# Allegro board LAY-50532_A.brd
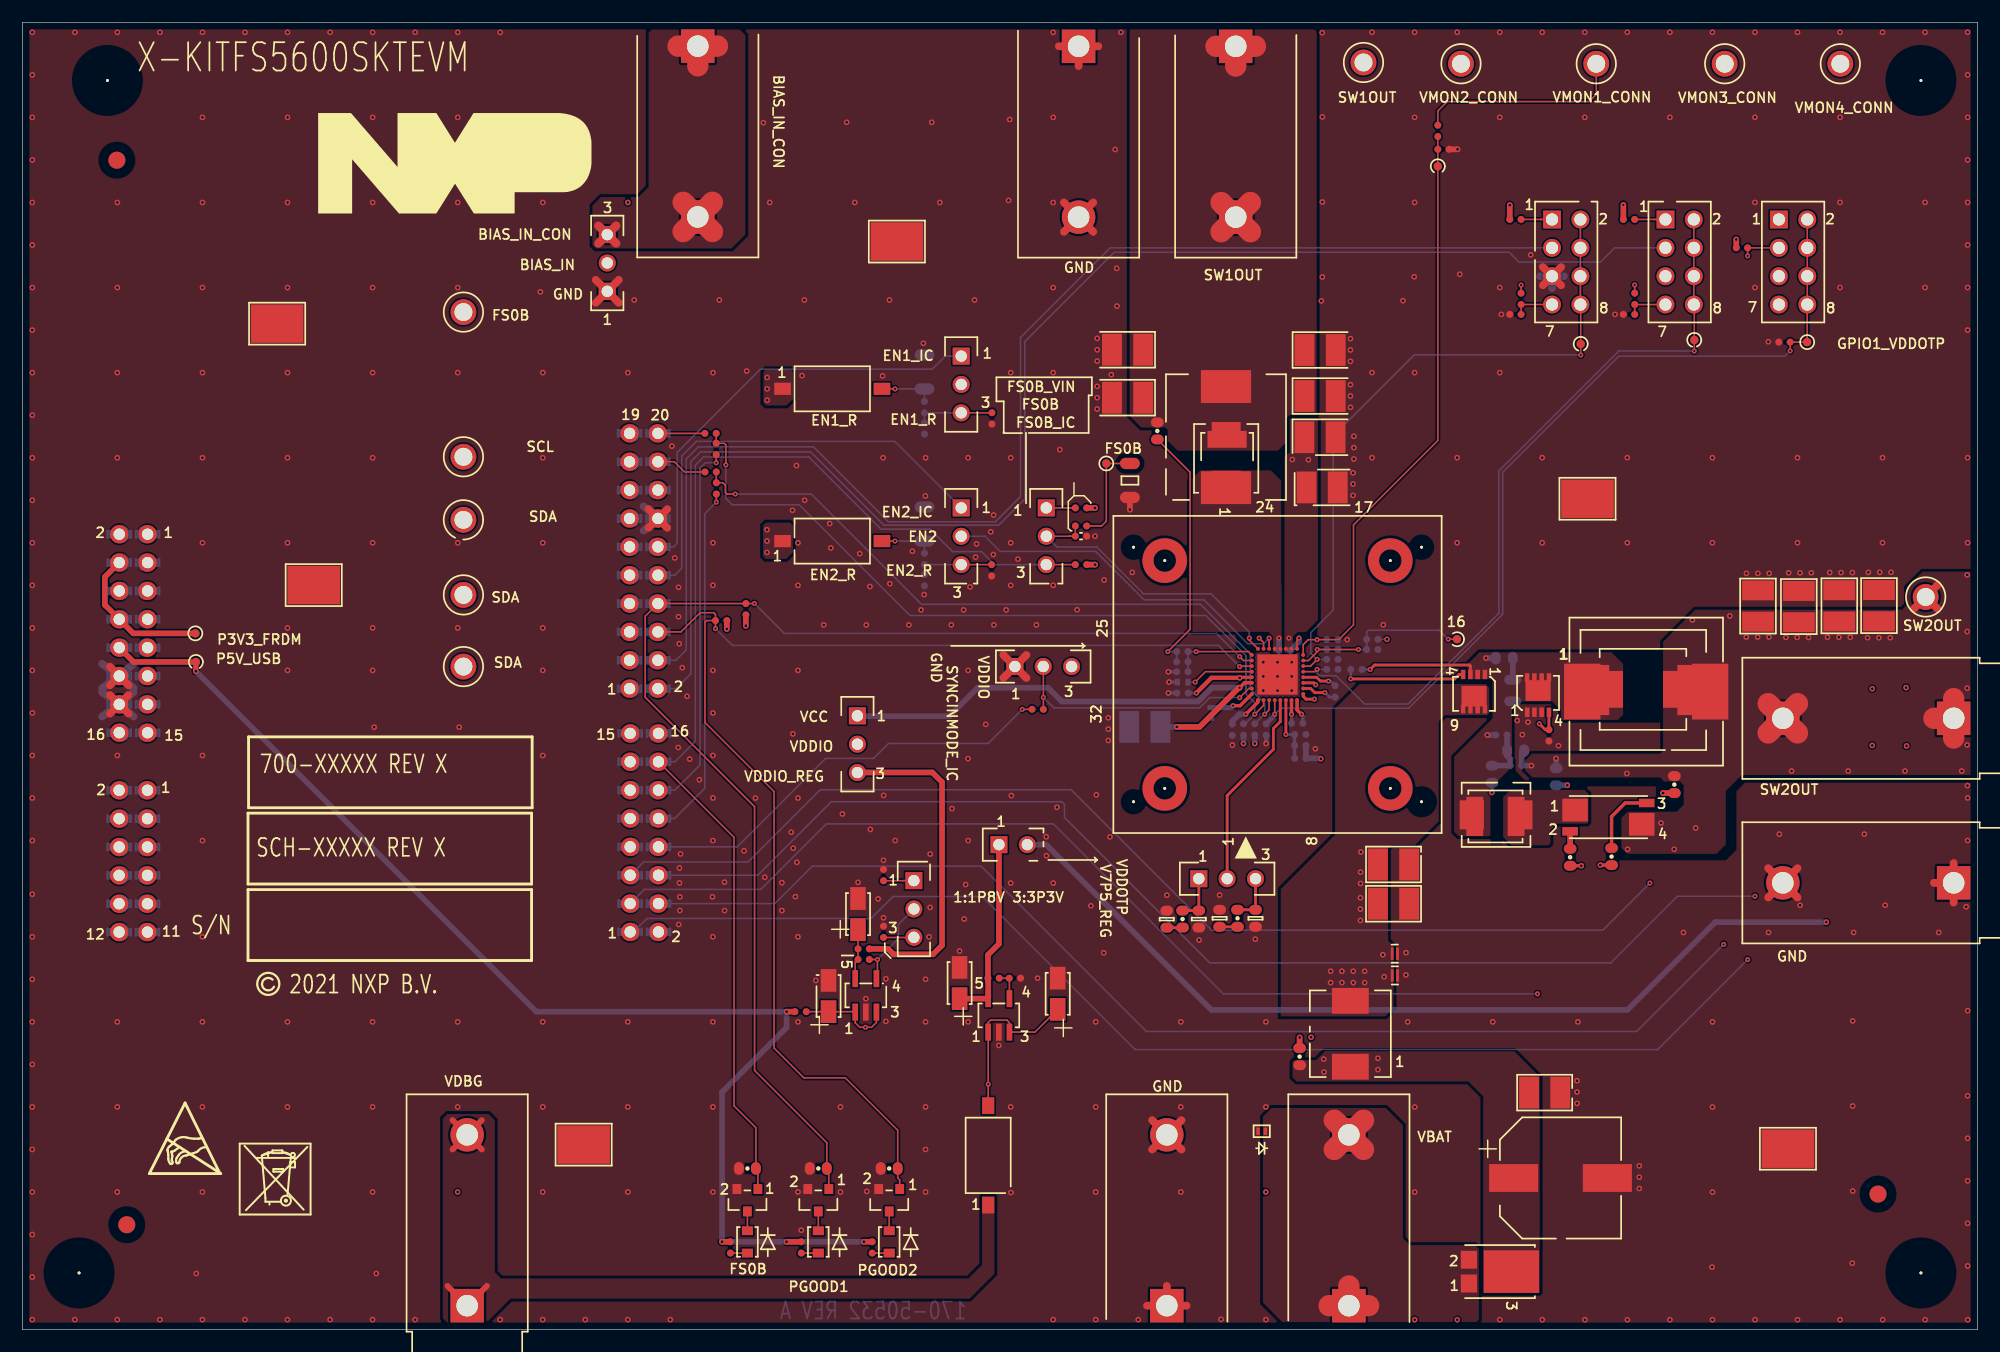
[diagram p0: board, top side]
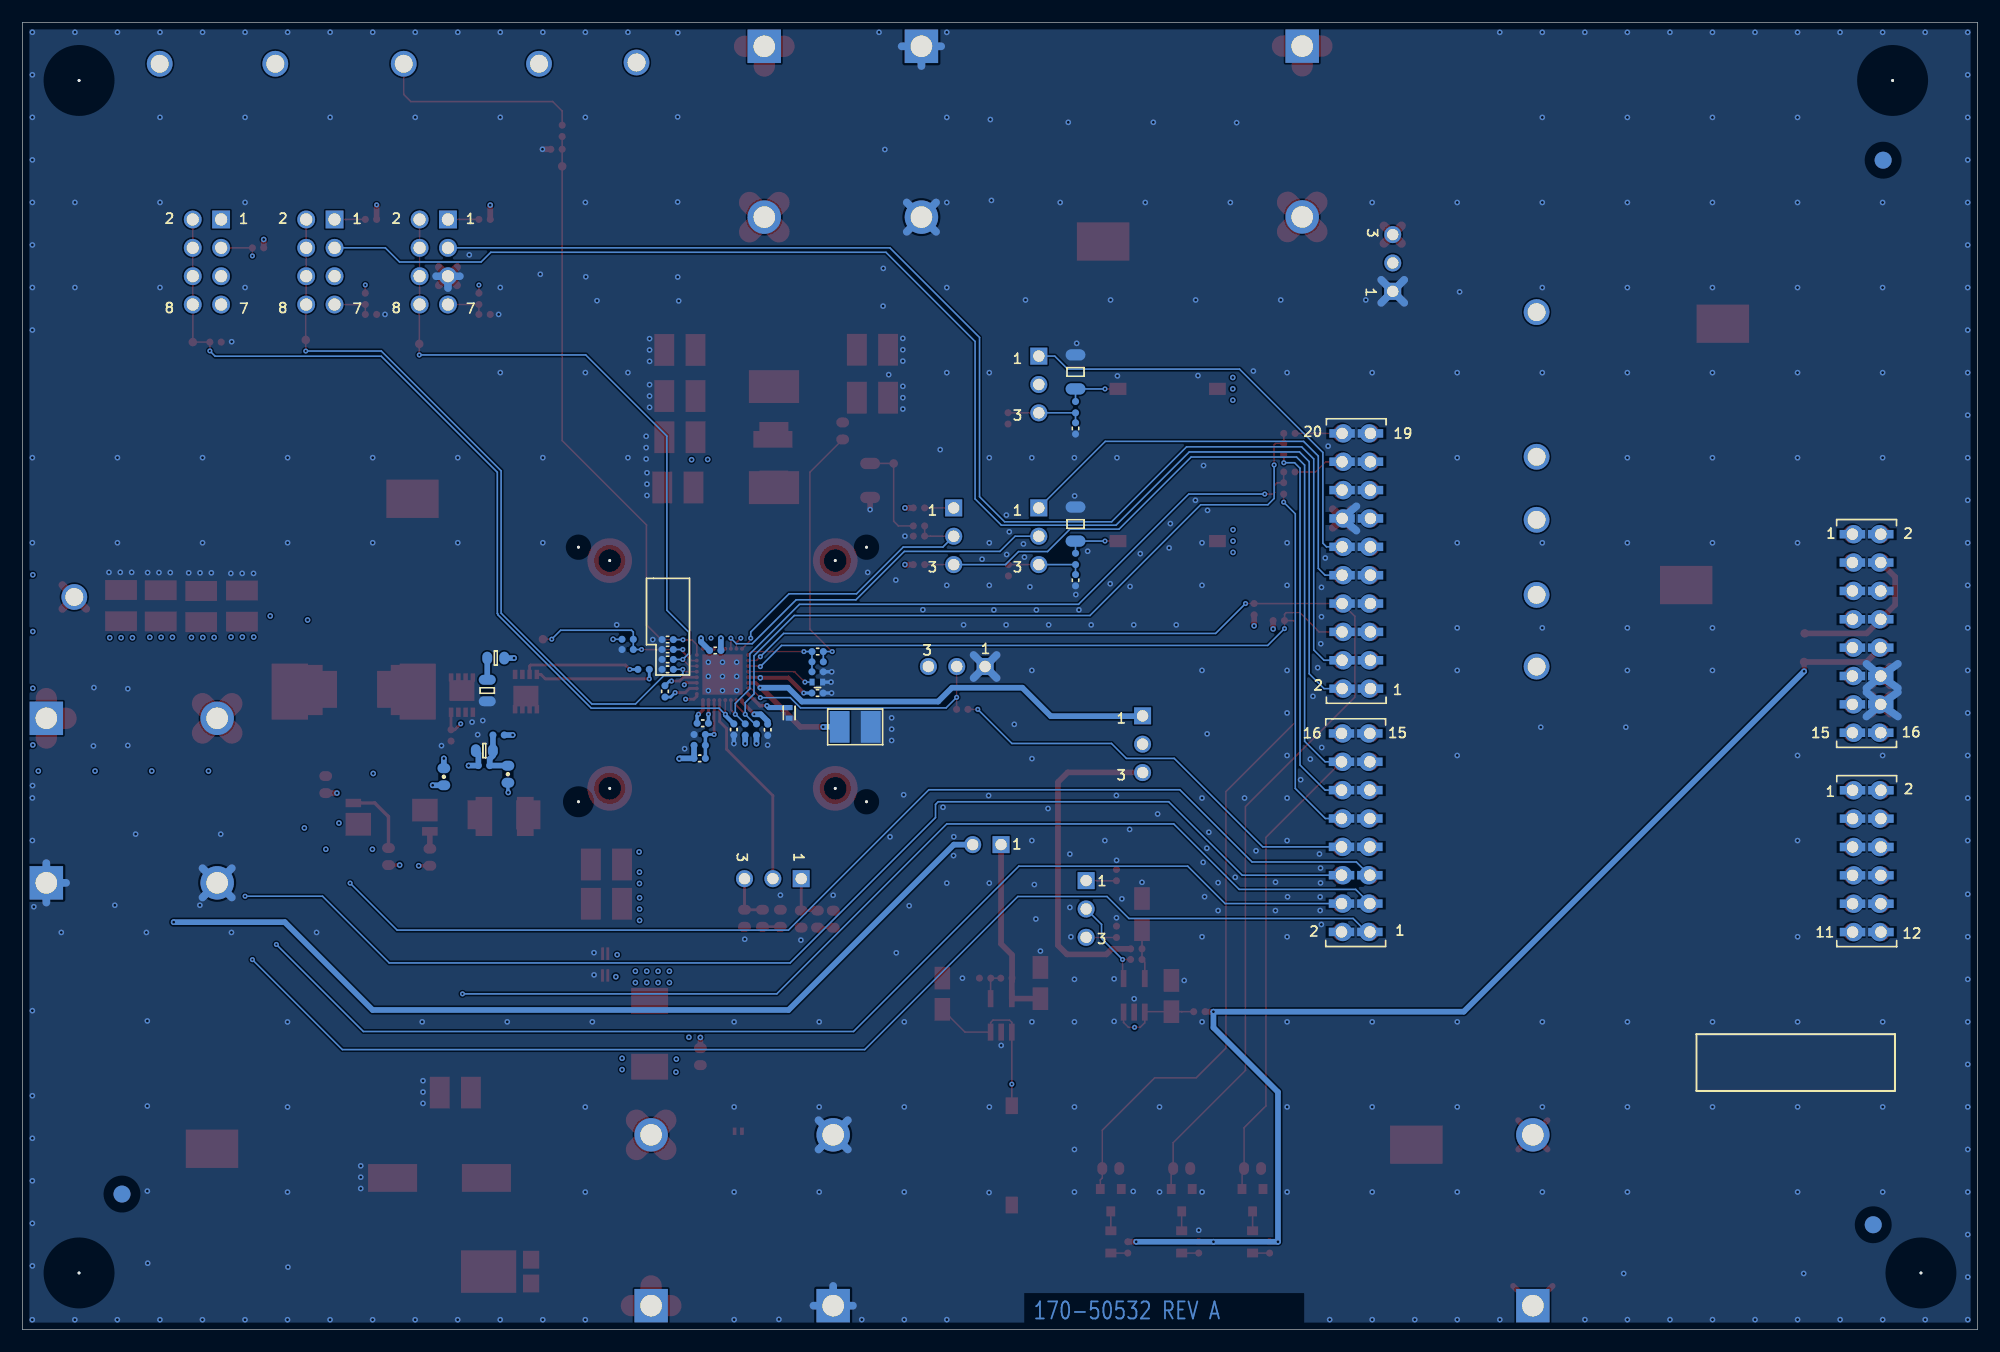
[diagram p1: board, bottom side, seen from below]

Outline 175.13 x 117.09 mm; copper layers: TOP, L2_GND1, L3_INT1, L4_PWR1, L5_GND2, L6_PWR2, L7_GND3, BOTTOM. Coordinates in mm from the lower left corner of the outline.
Outline path: 0,117.09 175.13,117.09 175.13,0 0,0 0,117.09

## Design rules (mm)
constraint set DEFAULT: min track width 0.14
net group POWER: nets VCC VDDIO

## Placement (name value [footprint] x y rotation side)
C1  10uF  [CC1210]  136.35 21.23 0 top
C2  47uF  [CAP_ALEL_10P5SQ_SMT]  137.77 13.59 90 top
C3  0.022UF  [CC1206_OV]  80.8 85.78 90 bottom
C4  6800pF  [CC0402_25]  80.8 80.72 270 bottom
C5  0.022UF  [CC1206_OV]  80.8 72.16 90 bottom
C6  6800pF  [CC0402_25]  80.8 67.13 270 bottom
C7  1uF  [CC0402_TOL0P2]  106.45 55.24 270 bottom
C8  0.1uF  [CC0402_25]  103.91 57.02 180 bottom
C9  10uF  [CC1210]  100.54 53.99 180 bottom
C10  2.2uF  [CC0402_TOL0P2]  103.93 58 180 bottom
C11  0.1uF  [CC0402_25]  108.37 53.73 270 bottom
C12  0.1uF  [CC0402_25]  113.07 60.83 180 bottom
C13  CGA6P1X7R1C226M250AC  [CC1210]  116.24 83.62 0 top
C14  CGA6P1X7R1C226M250AC  [CC1210]  116.24 87.75 0 top
C15  CGA6P1X7R1C226M250AC  [CC1210]  98.99 87.77 180 top
C16  CGA6P1X7R1C226M250AC  [CC1210]  98.99 83.48 180 top
C17  10uF  [CC1210]  116.23 79.93 0 top
C18  10uF  [CC1210]  116.42 75.44 0 top
C19  0.1uF  [CC0402_25]  117.58 57.17 270 bottom
C20  10uF  [CC1210]  122.82 41.67 0 top
C22  10uF  [CC1210]  122.82 38.15 0 top
C24  CGA6P1X7R1C226M250AC  [CC1210]  155.46 64.81 90 top
C25  CGA6P1X7R1C226M250AC  [CC1210]  159.12 64.77 90 top
C26  CGA6P1X7R1C226M250AC  [CC1210]  162.74 64.83 90 top
C27  CGA6P1X7R1C226M250AC  [CC1210]  166.29 64.85 90 top
C32  0.01UF  [CC0402_25]  117.33 61.81 0 bottom
C33  0.01UF  [CC0402_25]  117.33 60.92 0 bottom
C34  0.01UF  [CC0402_25]  117.33 60.03 0 bottom
C37  6800pF  [CC0402_25]  114.19 54.31 180 bottom
C42  0.022UF  [CC1206_OV]  99.2 76.06 270 top
C43  6800pF  [CC0402_25]  94.82 71.07 0 top
C44  1uF  [CC0402_25]  111.4 53.75 270 bottom
C45  2.2UF  [CC3216]  72.21 29.88 90 top
C46  2.2UF  [CC3216]  74.85 37.22 90 top
C47  2.2UF  [CC3216]  92.74 30.09 90 top
C48  2.2UF  [CC3216]  83.95 31.05 90 top
C49  2200pF  [CC0402_25]  103.9 60.73 0 bottom
C50  2200pF  [CC0402_25]  114.46 51.17 180 bottom
C51  2200PF  [CC0603_OV]  132.73 60.15 0 bottom
C52  0.1uF  [CC0603_OV]  133.75 51.86 0 bottom
C53  0.01UF  [CC0402_25]  117.33 59.14 0 bottom
C54  0.047uF  [CC0204]  122.93 31.73 0 top
C55  0.047uF  [CC0204]  122.93 33.68 0 top
CCOMP1  0.022UF  [CC0603_OV]  102.5 36.77 90 top
CCOMP2  0.022UF  [CC0603_OV]  107.23 36.85 90 top
CHF1  20pF  [CC0603_OV]  105.37 36.77 270 top
CHF2  20pF  [CC0603_OV]  110.45 36.85 270 top
D1  PMEG060V050EPD  [SOT1289]  132.34 5.2 270 top
D2  AQHV36-01ETG  [DIODE_SOD882_SM_0P7X1P1]  111.01 17.77 0 top
D7  RED  [LED2_2P1X1P5_NSP]  71.29 7.86 270 top
D8  RED  [LED2_2P1X1P5_NSP]  77.64 7.86 270 top
D9  RED  [LED2_2P1X1P5_NSP]  64.94 7.86 270 top
GPIO2_VMON3  -  [TPAD_030]  139.58 88.29 0 top
GPIO3_VMON4  -  [TPAD_030]  149.75 88.65 0 top
J3  HDR 1X3  [HDR103]  84.09 87.2 0 top
J4  HDR 1X3  [HDR103]  84.09 73.6 0 top
J5  HDR 1X3  [HDR103]  88.9 59.4 90 top
J6  5-146257-8  [HDR208_197X789_TH]  54.44 35.62 0 bottom
J8  HDR 1X3  [HDR103]  91.71 73.6 0 top
J12  HDR 2X4  [HDR2X4_2P54_TH]  137.01 99.44 0 top
J13  HDR 2X4  [HDR2X4_2P54_TH]  147.17 99.44 0 top
J14  HDR 2X4  [HDR2X4_2P54_TH]  157.33 99.44 0 top
J21  SKT RED  [CON_BANANA_571]  118.81 2.15 180 top
J22  SKT RED  [CON_BANANA_571]  60.5 114.96 0 top
J23  SKT RED  [CON_BANANA_571]  108.68 114.95 0 top
J24  SKT RED  [CON_BANANA_571]  172.98 54.76 270 top
J25  SKT BLACK  [CON_BANANA_571]  102.51 2.15 180 top
J27  SKT BLACK  [CON_BANANA_571]  94.6 114.95 0 top
J28  SKT BLACK  [CON_BANANA_571]  172.98 40.02 270 top
J29  HDR 1X3  [HDR103]  52.39 93 180 top
J30  HDR_1X3  [HDR103]  79.85 40.22 0 top
J32  HDR 1X2  [HDR102]  87.47 43.44 90 top
J73  6-146257-0  [HDR210_197X989_TH]  54.39 57.42 0 bottom
J75  5-146257-6  [HDR206_197X589_TH]  11.21 48.31 180 bottom
J91  5-146257-8  [HDR208_197X789_TH]  11.22 71.25 180 bottom
J92  SKT RED  [CON_BANANA_571]  39.84 2.15 180 top
J93  HDR 1X3  [HDR103]  74.8 54.98 0 top
J94  HDR 1X3  [HDR103]  105.37 40.39 90 top
L1  1uH  [IND2_7P4X6P9_SM]  118.95 26.51 90 top
L2  4.7uH  [IND2_10P9X10P4]  145.19 57.29 0 top
L3  VCHA042A-1R5MS6  [IND2_4P5X4P3]  107.91 77.9 90 top
L5  VCHA042A-1R5MS6  [IND2_4P5X4P3]  131.94 45.97 0 top
L6  6.8UH  [IND2_10P9X10P4]  107.81 79.94 90 top
L7  1.5UH  [IND_2_5P4X5P8]  107.82 78.04 90 top
L8  1.5UH  [IND_2_5P4X5P8]  132 46.11 0 top
L9  4.7uH  [IND2_13P4X12P9MM_SM]  145.45 57.15 0 top
L10  4.7uH  [IND2_7P4X6P9_SM]  145.16 57.35 0 top
NOREF  -  []  130.33 57.75 0 top
NOREF#2  -  []  113.67 60.98 0 top
NOREF#3  -  []  142.56 113.38 0 top
NOREF#4  -  []  53.21 54.53 0 top
NOREF#5  -  []  105.73 56.95 90 top
NOREF#6  -  []  99.52 70.08 0 top
NOREF#7  -  []  20.21 33.06 0 top
NOREF#8  -  []  41.09 78.18 0 top
NOREF#9  -  []  12.44 34.48 0 top
NOREF#10  -  []  114.17 56.38 90 top
NOREF#11  -  []  137.46 55.68 90 top
NOREF#12  -  []  138.75 50.7 0 top
NOREF#13  -  []  0 0 0 top
NOREF#14  -  []  110.68 17.77 0 top
NOREF#15  -  [unnamed#2]  9.35 9.4 0 top
NOREF#16  -  []  130.33 56.25 90 top
NOREF#17  -  []  41.09 72.54 0 top
NOREF#18  -  []  -12.96 -140.72 0 top
NOREF#19  -  []  111.56 17.42 90 top
NOREF#20  -  []  134.63 58.79 0 top
NOREF#21  -  []  103.45 58 0 top
NOREF#22  -  []  106.74 78.92 0 top
NOREF#23  -  []  106.8 55.84 0 top
NOREF#24  -  []  22.03 30.95 0 top
NOREF#25  -  []  154.06 113.38 0 top
NOREF#26  -  []  101.26 75.85 0 top
NOREF#27  -  []  110.12 60.43 0 top
NOREF#28  -  []  58.21 54.53 90 top
NOREF#29  -  []  130.9 44.82 0 top
NOREF#30  -  []  11.4 13.98 0 top
NOREF#31  -  []  102.32 68.88 0 top
NOREF#32  -  []  20.26 46.75 0 top
NOREF#33  -  []  12.45 52.34 0 top
NOREF#34  -  []  145.82 90.39 90 top
NOREF#35  -  []  41.09 59.39 0 top
NOREF#36  -  [unnamed#2]  8.47 104.75 0 top
NOREF#37  -  []  110.36 56.37 0 top
NOREF#38  -  []  142.21 57.35 0 top
NOREF#39  -  []  122.4 22.81 0 top
NOREF#40  -  []  69.34 68.79 0 top
NOREF#41  -  []  56.93 57.42 90 top
NOREF#42  -  []  155.98 90.39 0 top
NOREF#43  -  []  0 117.09 0 top
NOREF#44  -  []  164.42 113.38 0 top
NOREF#45  -  [unnamed#2]  5.08 5.08 0 top
NOREF#46  -  []  137.46 55.68 90 top
NOREF#47  -  []  125.32 47.28 90 top
NOREF#48  -  []  0 0 90 top
NOREF#49  -  []  134.81 57.73 0 top
NOREF#50  -  []  141.46 53.9 0 top
NOREF#51  -  []  104.92 75.74 0 top
NOREF#52  -  []  5.08 5.08 0 top
NOREF#53  -  []  -423.58 -337.38 0 top
NOREF#54  -  []  113.01 74.49 90 top
NOREF#55  -  []  140.66 57.29 0 top
NOREF#56  -  []  129.72 56.25 90 top
NOREF#57  -  []  145.02 18.84 90 top
NOREF#58  -  []  56.93 57.42 90 top
NOREF#59  -  []  75.74 82.43 90 top
NOREF#60  -  []  114.72 56.93 90 top
NOREF#61  -  []  104.53 57.65 0 top
NOREF#62  -  []  129.8 22.81 90 top
NOREF#63  -  []  134.78 55.3 0 top
NOREF#64  -  []  128.32 58.3 0 top
NOREF#65  -  []  -23.87 -149.8 90 top
NOREF#66  -  []  17.44 34.48 90 top
NOREF#67  -  []  68.09 84.27 0 top
NOREF#68  -  []  129.39 7.4 0 top
NOREF#69  -  []  130.35 58.69 0 top
NOREF#70  -  []  5.08 5.08 0 top
NOREF#71  -  []  126.95 44.66 90 top
NOREF#72  -  []  134.19 43.82 90 top
NOREF#73  -  []  23.49 -54.74 0 top
NOREF#74  -  []  122.52 48.48 90 top
NOREF#75  -  []  114.72 56.93 90 top
NOREF#76  -  []  68.09 70.63 0 top
NOREF#77  -  []  135.66 90.39 0 top
NOREF#78  -  []  152.15 50.7 90 top
NOREF#79  -  []  145.82 90.39 0 top
NOREF#80  -  []  20.21 39.91 0 top
NOREF#81  -  []  -23.87 -149.8 0 top
NOREF#82  -  []  26.49 99.98 0 top
NOREF#83  -  []  134.81 57.73 0 top
NOREF#84  -  []  129.1 43.81 0 top
NOREF#85  -  []  108 55.84 90 top
NOREF#86  -  []  53.16 81.41 0 top
NOREF#87  -  []  107.81 75.42 90 top
NOREF#88  -  []  133.57 13.59 0 top
NOREF#89  -  []  54.39 57.42 0 top
NOREF#90  -  []  64.94 6.86 90 top
NOREF#91  -  [unnamed#2]  170.05 5.08 0 top
NOREF#92  -  []  -23.87 -127 0 top
NOREF#93  -  []  105.76 75.85 90 top
NOREF#94  -  []  129.05 58.69 0 top
NOREF#95  -  []  -387.22 178.44 0 top
NOREF#96  -  []  155.98 90.39 90 top
NOREF#97  -  []  137.66 11.22 0 top
NOREF#98  -  []  105.32 75.34 90 top
NOREF#99  -  []  77.64 6.86 90 top
NOREF#100  -  []  134.63 58.79 0 top
NOREF#101  -  []  8.67 45.77 90 top
NOREF#102  -  []  5.08 5.08 0 top
NOREF#103  -  []  110.46 17.42 0 top
NOREF#104  -  []  118.95 23.56 90 top
NOREF#105  -  []  110.67 60.98 0 top
NOREF#106  -  []  41.09 91.14 0 top
NOREF#107  -  []  130.33 56.89 0 top
NOREF#108  -  []  130.44 113.38 0 top
NOREF#109  -  []  121.71 113.5 0 top
NOREF#110  -  []  71.29 6.86 90 top
NOREF#111  -  []  148.86 53.9 90 top
NOREF#112  -  []  0 0 90 top
NOREF#113  -  []  139.72 57.15 0 top
NOREF#114  -  []  8.68 68.71 90 top
NOREF#115  -  []  129.57 4.14 90 top
NOREF#116  -  []  19.47 10.31 0 top
NOREF#117  -  []  139.74 52.09 0 top
NOREF#118  -  []  75.74 68.79 90 top
NOREF#119  -  []  41.09 65.81 0 top
NOREF#120  -  [unnamed#2]  7.62 111.89 0 top
NOREF#121  -  []  58.16 81.41 90 top
NOREF#122  -  []  97.9 72.71 0 top
NOREF#123  -  []  129.39 3 90 top
NOREF#124  -  []  56.98 35.62 90 top
NOREF#125  -  []  8.68 71.25 0 top
NOREF#126  -  []  129.69 43.82 0 top
NOREF#127  -  []  88.35 12.41 0 top
NOREF#128  -  []  107.91 76.05 90 top
NOREF#129  -  []  129.5 43.41 90 top
NOREF#130  -  []  106.45 54.77 90 top
NOREF#131  -  []  135.66 90.39 90 top
NOREF#132  -  []  86.51 11.16 90 top
NOREF#133  -  []  69.34 82.43 0 top
NOREF#134  -  []  129.57 4.14 90 top
NOREF#135  -  [unnamed#2]  170.05 111.89 0 top
NOREF#136  -  []  135.76 57.55 0 top
NOREF#137  -  []  8.67 48.31 0 top
NOREF#138  -  []  17.46 52.34 90 top
NOREF#139  -  []  94.75 12.41 90 top
NOREF#140  -  []  131.72 57.9 90 top
NOREF#141  -  []  172.06 65.63 0 top
NOREF#142  -  []  54.44 35.62 0 top
NOREF#143  -  [unnamed#2]  166.21 12.15 0 top
NOREF#144  -  []  5.45 24.05 0 top
NOREF#145  -  []  130.09 45.97 0 top
NOREF#146  -  []  25.19 21.38 180 bottom
NOREF#147  -  [unnamed#2]  9.35 9.4 180 bottom
NOREF#148  -  [unnamed#2]  166.21 12.15 180 bottom
NOREF#149  -  [unnamed#2]  8.47 104.75 180 bottom
Q2  NX3008NBK  [SOT23_A]  71.29 11.59 180 top
Q3  NX3008NBK  [SOT23_A]  77.64 11.59 180 top
Q4  NX3008NBK  [SOT23_A]  64.94 11.59 180 top
Q15  BUK9M42-60EX  [LFPAK33_0P65_3P4X2P7]  130.02 57.15 270 top
Q16  BUK9M9R5-40HX  [LFPAK33_0P65_3P4X2P7]  135.76 56.83 90 top
R1  0  [RC0603_OV]  114.4 24.46 90 top
R2  5.1K  [RC0402_25]  80.8 82.63 90 bottom
R3  6.65K  [RC0402_25]  132.47 53.26 0 bottom
R6  5.1K  [RC0402_25]  80.8 69.03 90 bottom
R8  2.2K  [RC0402_25]  109.38 53.75 90 bottom
R9  2.2K  [RC0402_25]  110.39 53.75 90 bottom
R11  0  [RC0402_25]  103.9 59.82 180 bottom
R12  0  [RC0603_OV]  138.63 42.31 270 top
R13  2.2  [RC0805_OV]  133.49 57.24 270 bottom
R18  5.1K  [RC0402_25]  64.81 64.53 90 top
R19  5.1K  [RC0402_25]  62.59 63.51 180 top
R24  1M  [RC0402_25]  119.49 59.14 0 bottom
R25  1M  [RC0402_25]  136.73 53.23 270 top
R27  49.9  [RC0603_OV]  147.96 48.82 90 top
R28  5.1K  [RC0402_25]  94.82 68.52 0 top
R29  5.1K  [RC0402_25]  94.82 73.6 0 top
R30  5.1K  [RC0402_25]  94.82 71.99 0 top
R32  5.1K  [RC0402_25]  126.78 107.37 270 top
R33  5.1K  [RC0402_25]  120.92 61.83 180 bottom
R34  5.1K  [RC0402_25]  134.24 92.33 270 top
R35  5.1K  [RC0402_25]  144.41 92.33 270 top
R37  5.1K  [RC0402_25]  127.29 105.72 0 top
R38  5.1K  [RC0402_25]  120.92 60.92 0 bottom
R39  5.1K  [RC0402_25]  133.73 90.93 180 top
R40  5.1K  [RC0402_25]  143.91 90.93 180 top
R41  5.1K  [RC0402_25]  133.73 99.44 0 top
R42  5.1K  [RC0402_25]  143.91 99.44 0 top
R43  5.1K  [RC0402_25]  154.02 96.9 0 top
R44  280K  [RC0402_25]  157.83 88.45 180 top
R45  0  [RC0402_25]  69.71 28.48 180 top
R46  0  [RC0402_25]  75.36 34.11 180 top
R47  5.1K  [RC0402_25]  69.77 7.37 270 top
R48  5.1K  [RC0402_25]  76.12 7.37 270 top
R49  5.1K  [RC0402_25]  63.42 7.37 270 top
R50  169K  [RC0402_25]  75.36 33.16 0 top
R51  280K  [RC0402_25]  77.13 35.63 90 top
R52  76.8K  [RC0402_25]  77.13 40.71 90 top
R53  10K  [RC0402_25]  87 31.48 0 top
R54  54.9K  [RC0402_25]  88.9 31.48 0 top
R59  5.1K  [RC0402_25]  103.9 58.92 180 bottom
R60  49.9  [RC0603_OV]  101.66 80.5 90 top
R61  0  [RC0402_25]  114.46 52.34 0 bottom
R63  5.1K  [RC0402_25]  114.46 53.31 0 bottom
R64  0  [RC0402_25]  61.64 80.28 0 top
R65  0  [RC0402_25]  62.15 78.88 90 top
R66  0  [RC0402_25]  62.16 75.35 90 top
R67  0  [RC0402_25]  61.65 76.82 0 top
R69  510K  [RC0603_OV]  71.29 14.44 180 top
R70  510K  [RC0603_OV]  77.64 14.44 180 top
R71  510K  [RC0603_OV]  64.94 14.44 180 top
R72  1M  [RC0402_25]  86.84 81.62 270 top
R73  1M  [RC0402_25]  86.81 68.02 270 top
R74  6.65K  [RC0402_25]  133.78 50.52 0 bottom
R75  0  [RC0603_OV]  142.34 42.38 270 top
R76  0  [RC0603_OV]  131.64 49.75 90 bottom
R77  0  [RC0603_OV]  137.38 49.52 90 bottom
R78  0  [RC0402_25]  90.95 55.56 0 top
R79  0.02  [RC2512_4P_6P6X3P4]  142.06 45.9 0 top
RCOMP1  1.5K  [RC0603_OV]  103.92 36.77 270 top
RCOMP2  8.06K  [RC0603_OV]  108.84 36.85 270 top
SW1  A6S1104-H  [SW2_6P4X3P68_SM]  72.54 84.27 0 top
SW2  A6S1104-H  [SW2_6P4X3P68_SM]  72.54 70.63 0 top
SW3  A6S1104-H  [SW2_6P4X3P68_SM]  86.51 15.61 90 top
TP4  -  [TPAD_030]  15.49 62.37 0 top
TP5  -  [TPAD_030]  15.54 59.8 0 top
TP6  TESTLOOP  [TEST_PIN_TP107]  26.1 66.69 0 top
TP7  TESTLOOP  [TEST_PIN_TP107]  140.19 74.42 0 top
TP8  TESTLOOP  [TEST_PIN_TP107]  158.14 16.21 0 top
TP9  TESTLOOP  [TEST_PIN_TP107]  50.28 16.57 0 top
TP10  TESTLOOP  [TEST_PIN_TP107]  22.82 90.11 0 top
TP11  TESTLOOP  [TEST_PIN_TP107]  78.33 97.46 0 top
TP12  TESTLOOP_BLACK  [TP_TH_063]  39.51 65.81 0 top
TP13  TESTLOOP_BLACK  [TP_TH_063]  39.51 59.39 0 top
TP14  TESTLOOP_BLACK  [TP_TH_063]  39.51 91.14 0 top
TP15  TESTLOOP_BLACK  [TP_TH_063]  120.12 113.5 0 top
TP16  TESTLOOP_BLACK  [TP_TH_063]  170.48 65.63 0 top
TP17  TESTLOOP_BLACK  [TP_TH_063]  39.51 78.18 0 top
TP18  TESTLOOP_BLACK  [TP_TH_063]  39.51 72.54 0 top
TP19  TESTLOOP_BLACK  [TP_TH_063]  140.97 113.38 0 top
TP20  TESTLOOP_BLACK  [TP_TH_063]  128.85 113.38 0 top
TP21  TESTLOOP_BLACK  [TP_TH_063]  152.48 113.38 0 top
TP22  TESTLOOP_BLACK  [TP_TH_063]  162.83 113.38 0 top
TP23  -  [TPAD_030]  97.09 77.58 0 top
TP24  -  [TPAD_030]  159.86 88.45 0 top
U3  MIC5205  [SOT23-20X60-5]  75.55 29.94 0 top
U4  MIC5205  [SOT23-20X60-5]  87.46 28.15 0 top
U5  SKT_QFN32  [SKT_QFN32_0P5_28X29_SM]  112.42 58.68 90 top
VMON1  -  [TPAD_030]  126.78 104.2 0 top
VMON2  -  [TPAD_030]  128.5 61.84 0 top

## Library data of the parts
C1 C3-C20 C22 C24-C27 C32-C34 C37 C42-C44 C49-C53 CCOMP1 CCOMP2 CHF1 CHF2 = CAP_NP
C2 C45-C48 = CAP_POL
C54 C55 = CAP_NP_RVRS
D1 = DIODE_SCH_A1A2C3
D2 = DIODE_TVS
D7-D9 = LED
GPIO2_VMON3 GPIO3_VMON4 TP4-TP24 VMON1 VMON2 = TestLoop
J3-J5 J8 J29 J30 J93 J94 = CONN_HDR_3X1
J6 J91 = CONN_HDR_8X2
J12-J14 = CONN_HDR_4X2
J21-J25 J27 J28 J32 J92 = CONN_HDR_2X1
J73 = CONN_HDR_10X2
J75 = CONN_HDR_6X2
L1 L10 = INDP
L2 L3 L5-L9 = INDUCTOR
Q2-Q4 = NMOS_NX3008NBK
Q15 Q16 = NMOS_5P
R1 R3 R11-R13 R24 R25 R27 R44-R46 R50-R54 R60 R61 R64-R67 R69-R78 RCOMP1 RCOMP2 = RES
R2 R6 R8 R9 R18 R19 R28-R30 R32-R35 R37-R43 R47-R49 R59 R63 = RES: tolerance: 5%
R79 = RES_4PIN
SW1-SW3 = SW2P
U3 U4 = MIC5205YM5_5P
U5 = FS5600_QFN32

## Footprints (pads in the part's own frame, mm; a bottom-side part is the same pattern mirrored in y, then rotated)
CAP_ALEL_10P5SQ_SMT
  rect 2.489x4.394 smd: 1(0,4.2) 2(0,-4.2)
CC0204
  rect 0.254x1.118 smd: 1(-0.235,0) 2(0.235,0)
CC0402_25
  round 0.635 smd: 1(-0.508,0) 2(0.508,0)
CC0402_TOL0P2
  rect 0.457x0.61 smd: 1(-0.475,0) 2(0.475,0)
CC0603_OV
  oval 0.889x1.143 smd: 1(-0.762,0) 2(0.762,0)
CC1206_OV
  oval 1.016x1.778 smd: 1(-1.524,0) 2(1.524,0)
CC1210
  rect 1.778x2.845 smd: 1(-1.397,0) 2(1.397,0)
CC3216
  rect 2.032x1.397 smd: 1(-1.397,0) 2(1.397,0)
CON_BANANA_571
  rect 2.997x2.997 hole 1.93: 1(0,0)
  round 2.997 hole 1.93: 2(0,-15.3)
DIODE_SOD882_SM_0P7X1P1
  rect 0.33x0.66 smd: A(-0.325,0) C(0.325,0)
HDR2X4_2P54_TH
  rect 1.6x1.6 hole 1.092: 1(0,0)
  round 1.6 hole 1.092: 2(2.54,0) 3(0,-2.54) 4(2.54,-2.54) 5(0,-5.08) 6(2.54,-5.08) 7(0,-7.62) 8(2.54,-7.62)
HDR102
  rect 1.524x1.524 hole 1.016: 1(0,0)
  round 1.524 hole 1.016: 2(0,-2.54)
HDR103
  rect 1.524x1.524 hole 1.016: 1(0,0)
  round 1.524 hole 1.016: 2(0,-2.54) 3(0,-5.08)
HDR206_197X589_TH
  round 1.651 hole 1.016: 1(0,0) 2(2.54,0) 3(0,-2.54) 4(2.54,-2.54) 5(0,-5.08) 6(2.54,-5.08) 7(0,-7.62) 8(2.54,-7.62) 9(0,-10.16) 10(2.54,-10.16) 11(0,-12.7) 12(2.54,-12.7)
HDR208_197X789_TH
  round 1.651 hole 1.016: 1(0,0) 2(2.54,0) 3(0,-2.54) 4(2.54,-2.54) 5(0,-5.08) 6(2.54,-5.08) 7(0,-7.62) 8(2.54,-7.62) 9(0,-10.16) 10(2.54,-10.16) 11(0,-12.7) 12(2.54,-12.7) 13(0,-15.24) 14(2.54,-15.24) 15(0,-17.78) 16(2.54,-17.78)
HDR210_197X989_TH
  round 1.651 hole 1.016: 1(0,0) 2(2.54,0) 3(0,-2.54) 4(2.54,-2.54) 5(0,-5.08) 6(2.54,-5.08) 7(0,-7.62) 8(2.54,-7.62) 9(0,-10.16) 10(2.54,-10.16) 11(0,-12.7) 12(2.54,-12.7) 13(0,-15.24) 14(2.54,-15.24) 15(0,-17.78) 16(2.54,-17.78) 17(0,-20.32) 18(2.54,-20.32) 19(0,-22.86) 20(2.54,-22.86)
IND2_4P5X4P3
  rect 1.499x3.505 smd: 1(-1.85,0) 2(1.85,0)
IND2_7P4X6P9_SM
  rect 2.311x3.302 smd: 1(-2.95,0) 2(2.95,0)
IND2_10P9X10P4
  rect 2.946x4.496 smd: 1(-4.525,0) 2(4.525,0)
IND2_13P4X12P9MM_SM
  rect 3.251x5.004 smd: 1(-5.725,0) 2(5.725,0)
IND_2_5P4X5P8
  rect 2.159x2.591 smd: 1(-2.18,0) 2(2.18,0)
LED2_2P1X1P5_NSP
  rect 0.787x0.991 smd: A(1,0) C(-1,0)
LFPAK33_0P65_3P4X2P7
  rect 0.838x0.406 smd: 1(-1.535,0.975) 2(-1.535,0.325) 3(-1.535,-0.325) 4(-1.535,-0.975)
  custom 0.588x0.588 smd: 5(0.719,0)
RC0402_25
  round 0.635 smd: 1(-0.508,0) 2(0.508,0)
RC0603_OV
  oval 0.889x1.143 smd: 1(-0.762,0) 2(0.762,0)
RC0805_OV
  oval 0.889x1.524 smd: 1(-0.965,0) 2(0.965,0)
RC2512_4P_6P6X3P4
  rect 2.286x2.032 smd: 1(-2.985,0.635) 4(2.985,-0.635)
  rect 1.397x0.762 smd: 2(-3.429,-1.27) 3(3.429,1.27)
SKT_QFN32_0P5_28X29_SM
  round 0.254 hole 1.499 unplated: (-11.4,12.9) (11.4,12.9) (11.4,-12.9)
  round 0.254 hole 2.007 unplated: (-11.4,-12.9) (-10.2,10.1) (-10.2,-10.1) (10.2,10.1) (10.2,-10.1)
  round 0.356 smd: 1(-2.3,1.75) 2(-2.3,1.25) 3(-2.3,0.75) 4(-2.3,0.25) 5(-2.3,-0.25) 6(-2.3,-0.75) 7(-2.3,-1.25) 8(-2.3,-1.75) 9(-1.75,-2.3) 10(-1.25,-2.3) 11(-0.75,-2.3) 12(-0.25,-2.3) 13(0.25,-2.3) 14(0.75,-2.3) 15(1.25,-2.3) 16(1.75,-2.3) 17(2.3,-1.75) 18(2.3,-1.25) 19(2.3,-0.75) 20(2.3,-0.25) 21(2.3,0.25) 22(2.3,0.75) 23(2.3,1.25) 24(2.3,1.75) 25(1.75,2.3) 26(1.25,2.3) 27(0.75,2.3) 28(0.25,2.3) 29(-0.25,2.3) 30(-0.75,2.3) 31(-1.25,2.3) 32(-1.75,2.3)
  rect 3.607x3.607 smd: 33(0,0)
SOT23-20X60-5
  rect 0.508x1.524 smd: 1(-0.95,-1.499) 2(0,-1.499) 3(0.95,-1.499) 4(0.95,1.499) 5(-0.95,1.499)
SOT23_A
  rect 0.787x0.889 smd: 1(-0.94,-1.003) 2(0.94,-1.003) 3(0,1.003)
SOT1289
  rect 1.6x1.448 smd: 1(1.065,-2.776) 2(-1.065,-2.776)
  rect 3.81x4.953 smd: 3(0,1.024)
SW2_6P4X3P68_SM
  rect 1.499x1.092 smd: 1(-4.45,0) 2(4.45,0)
TEST_PIN_TP107
  rect 4.699x3.429 smd: 1(0,0)
TP_TH_063
  round 2.311 hole 1.6: 1(0,0)
TPAD_030
  round 0.762 smd: 1(0,0)
unnamed#2
  round 1.524 smd: (0,0)

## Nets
GND: C1.2 C2.2 C3.2 C4.2 C5.2 C6.2 C7.2 C8.2 C9.2 C10.2 C11.2 C13.2 C14.2 C15.2 C16.2 C17.2 C18.2 C20.2 C22.2 C24.2 C25.2 C26.2 C27.2 C32.2 C33.2 C34.2 C42.2 C43.2 C44.2 C45.2 C46.2 C47.2 C48.2 C53.2 C54.2 C55.2 CCOMP1.2 CCOMP2.2 CHF1.2 CHF2.2 D2.A J5.1 J12.5 J25.1 J25.2 J27.1 J27.2 J28.1 J28.2 J29.1 J73.14 J91.12 J91.14 Q2.2(SOURCE) Q3.2(SOURCE) Q4.2(SOURCE) Q16.1 Q16.2 Q16.3(S3) R13.2 R25.2 R37.2 R38.2 R39.2 R40.2 R44.2 R51.2 R52.2 R54.2 R59.2 R63.2 R69.2 R70.2 R71.2 R72.2 R73.2 TP6.1(PIN1) TP7.1(PIN1) TP8.1(PIN1) TP9.1(PIN1) TP10.1(PIN1) TP11.1(PIN1) U3.2 U4.2 U5.33
P3V3_FRDM: J91.4 J91.8 TP4.1(PIN1)
P5V_USB: J91.10 R45.2 R47.1 R48.1 R49.1 TP5.1(PIN1)
V7P5_REG: C48.1 J32.1 R53.1 U4.5(OUT)
VBAT: D1.1 D1.2 D2.C J21.1 J21.2
VBAT_S: C1.1 C2.1 D1.3(CATHODE) L1.1 R1.1 SW1.1 SW2.1
VCC: C9.1 J93.1 U5.30
VDDIO: C11.1 J5.3 J93.2 R8.1 R9.1 R18.1 R19.1 R28.2 R41.1 R42.1 R43.1 U5.1
VDDIO_REG: J93.3 R46.1
VDDOTP: J14.7 J32.2
VIN: C7.1 R1.2 R29.2 U5.32
BIAS_IN: C8.1 J29.2 U5.29
BIAS_IN_CON: J22.1 J22.2 J29.3
EN1: J3.2 U5.23
EN1_IC: J3.1 J73.12
EN1_R: C4.1 J3.3 R2.1 R72.1
EN2: J4.2 U5.22
EN2_IC: J4.1 J73.10
EN2_R: C6.1 J4.3 R6.1 R73.1
ERRMON1_IC: J6.6 J14.5
ERRMON2_IC: J6.4 J13.5
FCCU1_IC: J12.3 J73.4
FCCU2_IC: J13.3 J73.2
FS0B: C43.1 J8.2 R30.1 TP14.1(PIN1) U5.24
FS0B_IC: J6.14 J8.3 Q4.1 R28.1 R71.1
FS0B_VIN: J8.1 R29.1
GPIO1_VDDOTP: C44.1 J14.2 J14.4 J14.6 J14.8(B4) R44.1 TP24.1(PIN1) U5.4
GPIO2_VMON3: C34.1 GPIO2_VMON3.1(PIN1) J12.2 J12.4 J12.6 J12.8(B4) U5.14
GPIO3_VMON4: C53.1 GPIO3_VMON4.1(PIN1) J13.2 J13.4 J13.6 J13.8(B4) U5.13
GPO1_IC: J6.1 J14.3 R43.2
GPO2_IC: J6.3 J12.1 R41.2
GPO3_IC: J6.5 J13.1 R42.2
I2C_SCL_IC: R8.2 R64.2 R65.2 TP17.1(PIN1) U5.2
I2C_SDA_IC: R9.2 R66.2 R67.2 TP18.1(PIN1) U5.3
PGOOD1_IC: J73.8 Q2.1 R18.2 R69.1 TP12.1(PIN1) U5.26
PGOOD2_IC: J73.6 Q3.1 R19.2 R70.1 TP13.1(PIN1) U5.27
SW1FB: C49.2 R11.1 R59.1 U5.25
SW1FB_R: C49.1 R11.2 R60.1
SW1LX1: C12.2 L3.1 L6.1 L7.1 U5.20 U5.21
SW1OUT: C13.1 C14.1 C15.1 C16.1 J23.1 J23.2 L3.2 L6.2 L7.2 R60.2 TP15.1(PIN1)
SW2BOOT: C19.1 U5.12
SW2COMP: J94.2 U5.5
SW2CSN: C37.2 R75.2 R77.1 U5.7
SW2CSP: C37.1 R12.2 R76.1 U5.8
SW2FB: C50.2 R61.1 R63.1 U5.6
SW2FB_R: C50.1 R27.1 R61.2
SW2GHS: Q15.4 R24.1 U5.11
SW2GLS: Q16.4 R25.1 U5.9
SW2LX: C19.2 C51.1 L2.1 L5.1 L8.1 L9.1 L10.1 Q15.1 Q15.2 Q15.3(S3) Q16.5 R3.1 R24.2 U5.10
SW2OUT: C24.1 C25.1 C26.1 C27.1 C52.2 J24.1 J24.2 L2.2 L9.2 L10.2 R27.2 R74.2 R77.2 R79.4(I2) TP16.1(PIN1)
SWIN: C17.1 C18.1 C20.1 C22.1 C54.1 C55.1 L1.2 Q15.5 U5.18 U5.19
SYNCINMODE_IC: J5.2 R78.2 U5.31
VDIG: C10.1 U5.28
VMON1: C32.1 R32.2 R37.1 U5.16 VMON1.1(PIN1)
VMON1_CONN: R32.1 TP19.1(PIN1)
VMON2: C33.1 R33.2 R38.1 U5.15(VMON2) VMON2.1(PIN1)
VMON2_CONN: R33.1 TP20.1(PIN1)
VMON3_CONN: R34.1 TP21.1(PIN1)
VMON3_R: J12.7 R34.2 R39.1
VMON4_CONN: R35.1 TP22.1(PIN1)
VMON4_R: J13.7 R35.2 R40.1
N17950540: J6.12 R65.1
N17950546: J6.10 R66.1
N17950552: J6.8 R78.1
N18041286: C3.1 R2.2 SW1.2(NO)
N18053281: C5.1 R6.2 SW2.2(NO)
N18177905: C45.1 R45.1 U3.1 U3.3
N18177915: C46.1 R46.2 R50.1 U3.5(OUT)
N18177949: J30.2 R50.2 U3.4
N18177998: J30.3 R51.1
N18178006: J30.1 R52.1
N18178603: C47.1 SW3.2(NO) U4.1 U4.3
N18178669: R53.2 R54.1 U4.4
N18196092: J73.18 R67.1
N18196101: J73.20 R64.1
N18229657: D7.A R47.2
N18229660: D7.C(CATHODE) Q2.3
N18229791: D8.C(CATHODE) Q3.3
N18230808: D8.A R48.2
N18230892: D9.C(CATHODE) Q4.3
N18230895: D9.A R49.2
N18266548: J92.1 J92.2 SW3.1
N18367835: L5.2 L8.2 R79.1
N18368184: R12.1 R79.2
N18377789: C51.2 R13.1
N18378672: C52.1 R3.2 R74.1 R76.2
N18406944: R75.1 R79.3
N18465771: CHF1.1 J94.1 RCOMP1.1
N18465820: CHF2.1 J94.3 RCOMP2.1
N18465826: CCOMP1.1 RCOMP1.2
N18465873: CCOMP2.1 RCOMP2.2
N18468740: C42.1 R30.2 TP23.1(PIN1)
N18472203: C12.1 U5.17

Pads without a net: J6 2 7 9 11 13 15 16; J14 1; J73 1 3 5 7 9 11 13 15 16 17 19; J75 1 2 3 4 5 6 7 8 9 10 11 12; J91 1 2 3 5 6 7 9 11 13 15 16

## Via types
v1: diameter 0.457, hole 0.203, TOP to BOTTOM, 60 vias
v2: diameter 0.508, hole 0.254, TOP to BOTTOM, 560 vias
v3: diameter 0.508, hole 0.257, TOP to BOTTOM, 9 vias

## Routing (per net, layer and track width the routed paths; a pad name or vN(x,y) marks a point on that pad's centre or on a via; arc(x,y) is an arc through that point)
GND: length 533.8
  TOP w0.508: C42.2 v2(99.2,73.45) ; R37.2 v2(128.55,105.72)
  TOP w0.686: 87.87,58.37 J5.1 ; J5.1 89.93,58.37 ; J5.1 87.87,60.43 ; J5.1 89.93,60.43 ; J25.1 104.27,2.15 ; J25.1 100.74,2.15 ; J25.1 102.51,3.92 ; 56.09,71.82 J73.14 ; J73.14 57.76,71.82 ; J73.14 57.76,73.49 ; J73.14 56.09,73.49 ; J27.1 96.37,114.95 ; J27.1 92.84,114.95 ; J27.1 94.6,113.18 ; 7.84,56.84 J91.14 ; J91.14 9.52,56.84 ; J91.14 9.52,55.17 ; J91.14 7.84,55.17 ; 101.2,16.14 J25.2 ; J25.2 103.82,16.14 ; J25.2 101.2,18.76 ; J25.2 103.82,18.76 ; 7.84,57.71 J91.12 ; J91.12 9.52,57.71 ; J91.12 7.84,59.38 ; J28.2 159,38.71 ; J28.2 156.37,41.33 ; J28.2 156.37,38.71 ; J28.2 159,41.33 ; 93.29,98.33 J27.2 ; J27.2 93.29,100.96 ; J27.2 95.92,100.96 ; J27.2 95.92,98.33 ; 51.36,91.97 J29.1 ; J29.1 51.36,94.03 ; J29.1 53.42,91.97 ; J29.1 53.42,94.03 ; 136.19,95.17 J12.5 ; J12.5 136.19,93.54 ; J12.5 137.83,93.54 ; J12.5 137.83,95.17 ; 172.98,38.26 J28.1 ; J28.1 172.98,41.79 ; J28.1 171.22,40.02
  L2_GND1 w0.686: J5.1 89.69,60.19 ; J5.1 88.11,58.61 ; J5.1 88.11,60.19 ; J5.1 89.69,58.61 ; J28.1 172.98,41.79 ; J28.1 172.98,38.26 ; J28.1 171.22,40.02 ; 156.37,38.71 J28.2 ; J28.2 159,41.33 ; J28.2 156.37,41.33 ; J28.2 159,38.71 ; 136.19,95.17 J12.5 ; J12.5 137.83,95.17 ; J12.5 136.19,93.54 ; J12.5 137.83,93.54 ; J29.1 53.18,93.79 ; J29.1 53.18,92.21 ; J29.1 51.6,92.21 ; J29.1 51.6,93.79 ; J73.14 57.76,73.49 ; J73.14 56.09,71.82 ; J73.14 56.09,73.49 ; J73.14 57.76,71.82 ; 7.84,57.71 J91.12 ; J91.12 7.84,59.38 ; J91.12 9.52,57.71 ; J91.12 9.52,59.38 ; J27.2 95.92,98.33 ; J27.2 93.29,100.96 ; J27.2 95.92,100.96 ; J27.2 93.29,98.33 ; J91.14 9.52,56.84 ; J91.14 7.84,56.84 ; J91.14 9.52,55.17 ; J91.14 7.84,55.17 ; 92.84,114.95 J27.1 ; J27.1 96.37,114.95 ; J27.1 94.6,113.18 ; 101.2,16.14 J25.2 ; J25.2 103.82,18.76 ; J25.2 101.2,18.76 ; J25.2 103.82,16.14 ; 100.74,2.15 J25.1 ; J25.1 102.51,3.92 ; J25.1 104.27,2.15
  L3_INT1 w0.686: J5.1 89.69,58.61 ; J5.1 89.69,60.19 ; J5.1 88.11,60.19 ; J5.1 88.11,58.61 ; J91.14 9.52,56.84 ; J91.14 7.84,56.84 ; J91.14 7.84,55.17 ; J91.14 9.52,55.17 ; 93.29,98.33 J27.2 ; J27.2 95.92,100.96 ; J27.2 93.29,100.96 ; J27.2 95.92,98.33 ; 57.76,71.82 J73.14 56.09,71.82 ; J25.2 103.82,18.76 ; J25.2 101.2,18.76 ; J25.2 101.2,16.14 ; J25.2 103.82,16.14 ; 92.84,114.95 J27.1 ; J27.1 94.6,113.18 ; J27.1 96.37,114.95 ; J28.1 172.98,41.79 ; J28.1 172.98,38.26 ; J28.1 171.22,40.02 ; 7.84,57.71 J91.12 ; J91.12 7.84,59.38 ; J91.12 9.52,59.38 ; J91.12 9.52,57.71 ; 51.6,92.21 J29.1 ; J29.1 53.18,93.79 ; J29.1 51.6,93.79 ; J29.1 53.18,92.21 ; J28.2 159,41.33 ; J28.2 156.37,38.71 ; J28.2 159,38.71 ; J28.2 156.37,41.33 ; 136.19,95.17 J12.5 136.19,93.54 ; J25.1 102.51,3.92 ; J25.1 104.27,2.15 ; J25.1 100.74,2.15
  L4_PWR1 w0.686: 51.6,93.79 J29.1 ; J29.1 53.18,92.21 ; J29.1 51.6,92.21 ; J29.1 53.18,93.79 ; J91.12 9.52,57.71 ; J91.12 7.84,59.38 ; J91.12 7.84,57.71 ; J91.12 9.52,59.38 ; J12.5 137.83,93.54 ; J12.5 136.19,95.17 ; J12.5 137.83,95.17 ; J12.5 136.19,93.54 ; J25.2 103.82,16.14 ; J25.2 101.2,18.76 ; J25.2 103.82,18.76 ; J25.2 101.2,16.14 ; J28.2 159,38.71 ; J28.2 159,41.33 ; J28.2 156.37,41.33 ; J28.2 156.37,38.71 ; J91.14 9.52,56.84 ; J91.14 7.84,56.84 ; J91.14 9.52,55.17 ; J91.14 7.84,55.17 ; 93.29,100.96 J27.2 ; J27.2 93.29,98.33 ; J27.2 95.92,98.33 ; J27.2 95.92,100.96 ; 88.11,58.61 J5.1 ; J5.1 89.69,58.61 ; J5.1 89.69,60.19 ; J5.1 88.11,60.19 ; J25.1 102.51,3.92 ; J25.1 100.74,2.15 ; J25.1 104.27,2.15 ; J28.1 172.98,41.79 ; J28.1 171.22,40.02 ; J28.1 172.98,38.26 ; J73.14 57.76,73.49 ; J73.14 56.09,73.49 ; J73.14 57.76,71.82 ; J73.14 56.09,71.82 ; 92.84,114.95 J27.1 ; J27.1 94.6,113.18 ; J27.1 96.37,114.95
  L5_GND2 w0.686: J29.1 53.18,93.79 ; J29.1 51.6,92.21 ; J29.1 53.18,92.21 ; J29.1 51.6,93.79 ; 101.2,18.76 J25.2 ; J25.2 103.82,16.14 ; J25.2 103.82,18.76 ; J25.2 101.2,16.14 ; 7.84,56.84 J91.14 ; J91.14 9.52,55.17 ; J91.14 9.52,56.84 ; J91.14 7.84,55.17 ; J91.12 9.52,59.38 ; J91.12 9.52,57.71 ; J91.12 7.84,59.38 ; J91.12 7.84,57.71 ; 94.6,113.18 J27.1 ; J27.1 92.84,114.95 ; J27.1 96.37,114.95 ; 172.98,38.26 J28.1 ; J28.1 172.98,41.79 ; J28.1 171.22,40.02 ; J12.5 137.83,93.54 ; J12.5 137.83,95.17 ; J12.5 136.19,95.17 ; J12.5 136.19,93.54 ; J5.1 89.69,60.19 ; J5.1 88.11,60.19 ; J5.1 89.69,58.61 ; J5.1 88.11,58.61 ; 93.29,100.96 J27.2 ; J27.2 95.92,100.96 ; J27.2 95.92,98.33 ; J27.2 93.29,98.33 ; J73.14 57.76,73.49 ; J73.14 56.09,71.82 ; J73.14 57.76,71.82 ; J73.14 56.09,73.49 ; 156.37,38.71 J28.2 ; J28.2 159,38.71 ; J28.2 159,41.33 ; J28.2 156.37,41.33 ; 100.74,2.15 J25.1 ; J25.1 102.51,3.92 ; J25.1 104.27,2.15
  L6_PWR2 w0.686: 88.11,60.19 J5.1 ; J5.1 89.69,60.19 ; J5.1 88.11,58.61 ; J5.1 89.69,58.61 ; 94.6,113.18 J27.1 ; J27.1 96.37,114.95 ; J27.1 92.84,114.95 ; 93.29,98.33 J27.2 ; J27.2 95.92,100.96 ; J27.2 95.92,98.33 ; J27.2 93.29,100.96 ; 171.22,40.02 J28.1 ; J28.1 172.98,38.26 ; J28.1 172.98,41.79 ; J25.1 102.51,3.92 ; J25.1 104.27,2.15 ; J25.1 100.74,2.15 ; 101.2,16.14 J25.2 ; J25.2 101.2,18.76 ; J25.2 103.82,16.14 ; J25.2 103.82,18.76 ; J91.12 9.52,59.38 ; J91.12 7.84,59.38 ; J91.12 9.52,57.71 ; J91.12 7.84,57.71 ; J28.2 159,41.33 ; J28.2 159,38.71 ; J28.2 156.37,38.71 ; J28.2 156.37,41.33 ; J29.1 53.18,92.21 ; J29.1 51.6,93.79 ; J29.1 51.6,92.21 ; J29.1 53.18,93.79 ; 56.09,71.82 J73.14 ; J73.14 57.76,73.49 ; J73.14 57.76,71.82 ; J73.14 56.09,73.49 ; 136.19,95.17 J12.5 ; J12.5 136.19,93.54 ; J12.5 137.83,93.54 ; J12.5 137.83,95.17 ; J91.14 9.52,55.17 ; J91.14 7.84,56.84 ; J91.14 7.84,55.17 ; J91.14 9.52,56.84
  L7_GND3 w0.686: J12.5 137.83,93.54 ; J12.5 137.83,95.17 ; J12.5 136.19,93.54 ; J12.5 136.19,95.17 ; 100.74,2.15 J25.1 ; J25.1 102.51,3.92 ; J25.1 104.27,2.15 ; J29.1 53.18,93.79 ; J29.1 53.18,92.21 ; J29.1 51.6,93.79 ; J29.1 51.6,92.21 ; 171.22,40.02 J28.1 ; J28.1 172.98,41.79 ; J28.1 172.98,38.26 ; 88.11,58.61 J5.1 ; J5.1 89.69,58.61 ; J5.1 89.69,60.19 ; J5.1 88.11,60.19 ; J28.2 159,41.33 ; J28.2 156.37,41.33 ; J28.2 159,38.71 ; J28.2 156.37,38.71 ; J27.2 95.92,100.96 ; J27.2 93.29,98.33 ; J27.2 95.92,98.33 ; J27.2 93.29,100.96 ; J25.2 103.82,16.14 ; J25.2 103.82,18.76 ; J25.2 101.2,18.76 ; J25.2 101.2,16.14 ; 7.84,57.71 J91.12 ; J91.12 9.52,57.71 ; J91.12 9.52,59.38 ; J91.12 7.84,59.38 ; 7.84,56.84 J91.14 ; J91.14 9.52,56.84 ; J91.14 7.84,55.17 ; J91.14 9.52,55.17 ; 56.09,73.49 J73.14 ; J73.14 57.76,71.82 ; J73.14 56.09,71.82 ; J73.14 57.76,73.49 ; J27.1 96.37,114.95 ; J27.1 94.6,113.18 ; J27.1 92.84,114.95
  BOTTOM w0.305: C10.2 v2(102.7,58) ; R59.2 v2(102.64,58.92) ; C8.2 v2(102.65,57.02)
  BOTTOM w0.381: C44.2 111.4,52.5 v2(111.4,52.5)
  BOTTOM w0.686: 93.29,98.33 J27.2 ; J27.2 93.29,100.96 ; J27.2 95.92,100.96 ; J27.2 95.92,98.33 ; 7.14,57.45 J91.12 ; J91.12 9.96,59.64 ; J91.12 9.96,57.45 ; J91.12 7.14,59.64 ; 92.84,114.95 J27.1 ; J27.1 96.37,114.95 ; J27.1 94.6,113.18 ; 55.64,73.75 J73.14 55.64,71.56 ; 7.14,57.1 J91.14 ; J91.14 9.96,54.91 ; J91.14 7.14,54.91 ; J91.14 9.96,57.1 ; J25.1 102.51,3.92 ; J25.1 104.27,2.15 ; J25.1 100.74,2.15 ; 101.2,18.76 J25.2 ; J25.2 103.82,18.76 ; J25.2 103.82,16.14 ; J25.2 101.2,16.14 ; 51.36,94.03 J29.1 ; J29.1 53.42,94.03 ; J29.1 51.36,91.97 ; J29.1 53.42,91.97 ; 137.01,93.29 J12.5 ; J12.5 138.08,94.36 ; J12.5 135.94,94.36 ; J28.1 172.98,41.79 ; J28.1 171.22,40.02 ; J28.1 172.98,38.26 ; J5.1 89.93,60.43 ; J5.1 89.93,58.37 ; J5.1 87.87,60.43 ; J5.1 87.87,58.37 ; 156.37,41.33 J28.2 ; J28.2 159,38.71 ; J28.2 159,41.33 ; J28.2 156.37,38.71
  vias: v2(0.89,116.2) v2(0.89,112.39) v2(0.89,108.58) v2(0.89,104.77) v2(0.89,100.96) v2(0.89,97.15) v2(0.89,93.34) v2(0.89,89.53) v2(0.89,85.72) v2(0.89,81.91) v2(0.89,78.1) v2(0.89,74.29) v2(0.89,70.48) v2(0.89,66.67) v2(0.89,62.86) v2(0.89,59.05) v2(0.89,55.24) v2(0.89,51.43) v2(0.89,47.62) v2(0.89,43.81) v2(0.89,39) v2(0.89,35.19) v2(0.89,31.38) v2(0.89,27.57) v2(0.89,23.76) v2(0.89,19.95) v2(0.89,16.14) v2(0.89,12.33) v2(0.89,8.52) v2(0.89,4.71) v2(0.89,0.9) v2(4.7,116.2) v2(4.7,0.9) v2(8.51,116.2) v2(8.51,100.96) v2(8.51,93.34) v2(8.51,85.72) v2(8.51,78.1) v2(8.51,51.43) v2(8.51,27.57) v2(8.51,19.95) v2(8.51,12.33) v2(8.51,0.9) v2(12.32,116.2) v2(12.32,0.9) v2(15.58,5.03) v2(16.13,35.19) v2(16.13,27.57) v2(16.13,19.95) v2(16.13,12.33) v2(16.13,0.9) v2(16.13,116.2) v2(16.13,108.58) v2(16.13,100.96) v2(16.13,93.34) v2(16.13,85.72) v2(16.13,78.1) v2(16.13,70.48) v2(16.13,51.43) v2(16.13,43.81) v2(19.94,116.2) v2(19.94,0.9) v2(23.75,116.2) v2(23.75,108.58) v2(23.75,100.96) v2(23.75,93.34) v2(23.75,85.72) v2(23.75,78.1) v2(23.75,70.48) v2(23.75,62.86) v2(23.75,59.05) v2(23.75,27.57) v2(23.75,19.95) v2(23.75,0.9) v2(27.56,116.2) v2(27.56,0.9) v2(31.37,116.2) v2(31.37,108.58) v2(31.37,100.96) v2(31.37,93.34) v2(31.37,85.72) v2(31.37,78.1) v2(31.37,70.48) v2(31.37,62.86) v2(31.37,59.05) v2(31.37,27.57) v2(31.37,19.95) v2(31.37,12.33) v2(31.37,0.9) v2(31.51,53.96) v2(31.71,5.03) v2(35.18,116.2) v2(35.18,0.9) v2(38.99,116.2) v2(38.99,108.58) v2(38.99,100.96) v2(38.99,93.34) v2(38.99,85.72) v2(38.99,70.48) v2(38.99,62.86) v2(38.99,27.57) v2(38.99,19.95) v2(38.99,12.33) v2(39.13,53.96) v2(42.8,116.2) v2(42.8,0.9) v2(46.4,92.95) v2(46.61,100.96) v2(46.61,85.72) v2(46.61,78.1) v2(46.61,70.48) v2(46.61,62.86) v2(46.61,59.05) v2(46.61,51.43) v2(46.61,27.57) v2(46.61,19.95) v2(46.61,12.33) v2(46.61,0.9) v2(50.42,0.9) v2(54.23,27.57) v2(54.23,19.95) v2(54.23,12.33) v2(54.23,0.9) v2(54.23,100.96) v2(54.23,85.72) v2(54.8,92.23) v2(58.04,0.9) v2(58.18,79.13) v2(58.43,69.12) v2(58.77,66.49) v2(58.77,63.86) v2(58.75,52.14) v2(58.78,36.29) v2(58.84,61.44) v2(58.86,41.34) v2(58.86,40.02) v2(58.89,38.76) v2(58.89,37.54) v2(58.95,42.6) v2(59.11,59.29) v2(59.54,56.73) v2(59.77,51.1) v2(60.64,49.26) v2(61.81,38.77) v2(61.85,85.72) v2(61.85,70.48) v2(61.85,66.67) v2(61.85,59.05) v2(61.85,55.24) v2(61.85,51.43) v2(61.85,47.62) v2(61.85,43.81) v2(61.85,35.19) v2(61.85,27.57) v2(61.85,19.95) v2(61.85,12.33) v2(62.42,92.23) v2(62.89,40.08) v2(62.9,37.54) v2(64.64,42.89) v2(64.87,85.86) v2(65.66,47.62) v2(66.37,108.11) v2(66.5,40.52) v2(66.93,100.96) v2(68.03,40.04) v2(68.03,37.54) v2(68.86,44.55) v2(68.98,73.38) v2(69.01,53.37) v2(69.04,43.12) v2(69.24,38.78) v2(69.34,77.4) v2(69.37,41.86) v2(69.47,70.48) v2(69.47,66.67) v2(69.47,59.05) v2(69.47,47.62) v2(69.47,35.19) v2(69.47,27.57) v2(69.47,12.33) v2(69.77,8.9) v2(69.84,85.45) v2(70.04,92.23) v2(70.06,74.28) v2(71.07,31.28) v2(71.78,63.13) v2(72.31,72.2) v2(72.42,70.02) v2(73.28,19.95) v2(73.28,12.33) v2(73.45,46.19) v2(73.83,108.14) v2(74.55,100.96) v2(74.85,40.07) v2(75,69.51) v2(75.59,63.13) v2(75.55,29.64) v2(75.63,12.38) v2(75.92,66.56) v2(75.96,44.8) v2(76.65,38.59) v2(77.05,85.43) v2(77.09,78.1) v2(77.13,42.04) v2(77.14,47.85) v2(77.13,36.89) v2(77.34,31.42) v2(77.34,27.61) v2(77.66,92.23) v2(77.7,66.81) v2(78.18,43.81) v2(79.4,63.13) v2(79.72,69.72) v2(80.5,64.47) v2(80.7,88.34) v2(80.78,65.84) v2(80.9,78.1) v2(80.88,74.68) v2(80.9,31.38) v2(80.9,27.57) v2(80.9,19.95) v2(80.9,16.14) v2(80.9,12.33) v2(81.22,35.18) v2(81.31,42.6) v2(81.31,37.82) v2(81.45,108.14) v2(82.17,100.96) v2(83.21,63.13) v2(83.27,46.68) v2(83.95,33.91) v2(84.31,64.47) v2(84.36,36.78) v2(84.49,39.87) v2(84.71,78.1) v2(84.71,59.05) v2(84.7,51.15) v2(84.71,43.81) v2(84.71,27.57) v2(84.88,66.53) v2(85.28,92.23) v2(85.38,69.19) v2(85.47,70.38) v2(86.29,54.22) v2(86.73,71.46) v2(86.99,72.96) v2(86.97,69.43) v2(87.02,63.13) v2(87.46,25.46) v2(88.12,64.47) v2(88.33,101.14) v2(88.43,108.39) v2(88.52,85.72) v2(88.52,78.1) v2(88.52,70.48) v2(88.52,66.67) v2(88.52,40) v2(88.52,19.95) v2(88.59,47.84) v2(88.54,12.28) v2(89.17,69.01) v2(90.83,63.13) v2(90.93,31.48) v2(91.71,44.15) v2(91.73,42.46) v2(92.33,0.9) v2(92.33,116.2) v2(92.33,108.58) v2(92.33,100.96) v2(92.33,93.34) v2(92.33,85.72) v2(92.33,66.67) v2(92.33,40) v2(92.67,46.79) v2(92.92,78.82) v2(94.47,64.48) v2(95.7,37.97) v2(96.08,71.07) v2(96.2,47.91) v2(96.14,27.57) v2(96.14,19.95) v2(96.14,12.33) v2(96.14,0.9) v2(96.27,88.78) v2(96.27,87.77) v2(96.27,86.75) v2(96.27,84.49) v2(96.27,83.48) v2(96.27,82.46) v2(96.9,67.14) v2(96.85,33.76) v2(97.27,54.8) v2(97.27,53.79) v2(97.27,52.77) v2(97.42,44.14) v2(97.54,85.54) v2(97.88,105.7) v2(98.02,95.06) v2(98.04,91.68) v2(98.4,116.2) v2(99.42,67.83) v2(99.95,0.9) v2(102.51,38.91) v2(103.76,27.57) v2(103.76,19.95) v2(103.76,12.33) v2(105.4,34.89) v2(107.23,38.92) v2(107.37,0.92) v2(108.38,52.36) v2(110.43,34.97) v2(111.38,27.57) v2(111.38,19.95) v2(111.38,12.33) v2(111.38,0.9) v2(115.81,52.03) v2(116.42,116.16) v2(116.35,92.14) v2(116.44,108.62) v2(116.44,101) v2(116.43,94.28) v2(118.67,61.81) v2(118.95,88.76) v2(118.95,87.75) v2(118.95,86.73) v2(118.95,84.64) v2(118.95,83.62) v2(118.95,82.61) v2(119.19,76.75) v2(119.19,75.73) v2(119.19,74.72) v2(119.26,80.02) v2(119.26,79) v2(119.26,77.99) v2(120.89,116.2) v2(120.89,85.72) v2(120.89,78.1) v2(121.9,63.13) v2(123.66,92.16) v2(123.92,31.77) v2(123.93,33.77) v2(124.08,27.57) v2(124.7,116.2) v2(124.7,108.58) v2(124.7,100.96) v2(124.67,94.3) v2(124.7,85.72) v2(124.71,19.94) v2(124.71,12.32) v2(124.71,0.89) v2(128.51,116.2) v2(128.51,78.1) v2(128.51,70.48) v2(128.52,0.89) v2(128.74,94.53) v2(131.7,27.57) v2(132.32,116.2) v2(132.32,108.58) v2(132.32,93.34) v2(132.32,85.72) v2(132.33,0.89) v2(132.47,90.93) v2(133.89,54.56) v2(134.35,53.3) v2(134.85,54.41) v2(135.1,96.27) v2(136.13,116.2) v2(136.13,78.1) v2(136.13,70.48) v2(136.14,0.89) v2(137.59,52.3) v2(139.32,27.57) v2(139.25,22.3) v2(139.25,21.28) v2(139.25,20.27) v2(139.94,116.2) v2(139.94,108.58) v2(139.95,0.89) v2(142.65,90.93) v2(143.75,116.2) v2(143.75,78.1) v2(143.75,70.48) v2(143.76,0.89) v2(144.82,14.67) v2(144.82,13.66) v2(144.82,12.64) v2(147.56,116.2) v2(147.56,108.58) v2(147.57,0.89) v2(148.78,35.58) v2(151.37,116.2) v2(151.37,78.1) v2(151.37,70.48) v2(151.38,27.56) v2(151.38,19.94) v2(151.38,12.32) v2(151.34,5.6) v2(151.38,0.89) v2(154.43,67.74) v2(155.18,116.2) v2(155.18,108.58) v2(155.18,100.96) v2(155.18,93.34) v2(155.19,0.89) v2(155.44,67.74) v2(156.39,88.49) v2(156.4,35.58) v2(156.46,67.74) v2(157.37,44.38) v2(158.2,67.79) v2(158.99,116.2) v2(158.99,78.1) v2(158.99,70.48) v2(159,0.89) v2(159.22,67.79) v2(159.23,38.01) v2(160.23,67.79) v2(161.88,67.81) v2(162.8,116.2) v2(162.8,108.58) v2(162.8,100.96) v2(162.8,93.34) v2(162.81,0.89) v2(162.9,67.81) v2(163.91,67.81) v2(163.91,5.95) v2(164.02,35.58) v2(163.94,27.65) v2(163.94,20.03) v2(163.94,12.41) v2(164.99,44.38) v2(165.34,67.83) v2(165.69,57.41) v2(165.69,52.33) v2(166.36,67.83) v2(166.61,116.2) v2(166.61,78.1) v2(166.61,70.48) v2(166.62,0.89) v2(166.85,38.01) v2(167.38,67.83) v2(168.72,57.51) v2(168.77,52.28) v2(170.42,116.2) v2(170.42,100.96) v2(170.42,93.34) v2(170.43,0.89) v2(171.64,35.58) v2(174.1,37.88) v2(174.22,48.73) v2(174.23,116.2) v2(174.23,112.39) v2(174.23,108.58) v2(174.23,104.77) v2(174.23,100.96) v2(174.23,97.15) v2(174.23,93.34) v2(174.23,89.53) v2(174.23,78.1) v2(174.23,70.48) v2(174.23,47.62) v2(174.23,43.81) v2(174.23,28.57) v2(174.23,20.95) v2(174.23,17.14) v2(174.23,13.33) v2(174.23,9.52) v2(174.23,5.71) v2(174.24,0.89) v3(111.15,59.78) v3(111.15,58.51) v3(111.15,57.24) v3(112.42,59.78) v3(112.42,58.51) v3(112.42,57.24) v3(113.69,59.78) v3(113.69,58.51) v3(113.69,57.24)
P3V3_FRDM: length 13.5
  TOP w0.508: TP4.1 9.94,62.37 J91.8 7.39,64.92 7.39,67.42 J91.4
P5V_USB: length 113
  TOP w0.457: TP5.1 v2(15.54,58.97)
  TOP w0.508: TP5.1 9.97,59.8 J91.10 ; R47.1 v2(68.45,7.88) ; R49.1 v2(62.67,7.88) ; R45.2 v2(68.45,28.48) ; v2(75.37,7.88) R48.1
  BOTTOM w0.508: v2(15.54,58.97) 46.03,28.48 v2(68.45,28.48) 68.45,27.06 62.67,21.28 v2(62.67,7.88) v2(68.45,7.88) v2(75.37,7.88)
V7P5_REG: length 16.8
  TOP w0.508: J32.1 87.47,34.55 86.49,33.57 R53.1 86.49,31.23 86.51,31.21 U4.5 C48.1
VBAT: length 12.7
  TOP w1.905: 117.5,18.76 J21.2 ; J21.2 117.5,16.14 ; J21.2 120.13,16.14 ; J21.2 120.13,18.76 ; 117.05,2.15 J21.1 ; J21.1 118.81,3.92 ; J21.1 120.58,2.15
VBAT_S:
  vias: v2(66.72,85.28) v2(66.72,84.27) v2(66.72,83.25) v2(66.69,71.65) v2(66.69,70.63) v2(66.69,69.62) v2(116.56,24.23) v2(116.59,23.07) v2(121.41,24.31) v2(121.41,23.29)
VCC: length 46.2
  TOP w0.305: U5.30 109.47,57.93 v1(109.03,57.5)
  TOP w0.508: v2(103.4,53.99) 105.45,53.99 108.96,57.5 v1(109.03,57.5)
  BOTTOM w0.508: J93.1 74.83,54.95 83.02,54.95 85.56,57.5 91.87,57.5 93.11,56.26 105.3,56.26 106.54,57.5 v1(109.03,57.5) ; C9.1 v2(103.4,53.99)
VDDIO: length 168.2
  TOP w0.305: v1(109.58,55.12) 110.67,56.22 U5.1
  TOP w0.508: R41.1 v2(133.22,100.72) ; R43.1 v2(153.51,97.65) ; R42.1 v1(143.4,100.74) ; R19.1 v2(63.1,62.76) ; R18.1 v2(64.81,63.05) ; R28.2 v2(96.08,68.52)
  L3_INT1 w0.508: J5.3 98.26,55.12 v1(109.58,55.12)
  L4_PWR1 w0.508: v2(153.51,97.65) 153.51,100.31 153.08,100.74 v1(143.4,100.74) 133.24,100.74 v2(133.22,100.72) 128.66,100.72 108.37,80.43 108.37,62.38 110.09,60.66 110.09,56.13 109.58,55.61 v1(109.58,55.12) 109.38,54.92 v2(109.38,52.5) v2(110.39,52.5) ; v2(63.1,62.76) 63.38,63.05 v2(64.81,63.05) 64.81,55.25 67.62,52.44 J93.2 88.52,52.44 93.98,57.9 J5.3 96.08,61.5 v2(96.08,68.52)
  BOTTOM w0.508: v1(109.58,55.12) 109,55.12 108.37,54.49 C11.1 ; R9.1 v2(110.39,52.5) ; R8.1 v2(109.38,52.5)
VDDIO_REG: length 29.6
  TOP w0.508: R46.1 77.54,34.11 78.04,33.61 81.57,33.61 82.38,34.42 82.38,49.04 81.5,49.91 74.81,49.91 J93.3
VDDOTP: length 138
  L3_INT1 w0.508: v2(161.58,36.5) 160.99,37.09 160.99,88.16 J14.7
  BOTTOM w0.508: v2(161.58,36.5) 151.63,36.5 143.76,28.63 106.51,28.63 91.7,43.44 J32.2
VIN: length 5.9
  TOP w0.305: U5.32 109.07,55.88 v1(108.44,55.88)
  TOP w0.508: R29.2 v2(96.08,73.6) ; R1.2 v2(114.4,26.17)
  BOTTOM w0.457: v1(108.44,55.88) 108.28,55.72 C7.1
  vias: v2(115.43,26.19)
BIAS_IN: length 82.9
  TOP w0.279: v2(109.03,58.39) 109.08,58.43 U5.29
  TOP w0.381: v2(109.03,58.39) 106.51,58.39 v1(105.14,57.02)
  L3_INT1 w0.508: J29.2 68.41,95.54 87.11,76.83 91.46,76.83 97.64,70.66 97.64,62.92 100.88,59.68 105.34,59.68 106.63,58.39 v2(109.03,58.39)
  BOTTOM w0.279: C8.1 v1(105.14,57.02)
BIAS_IN_CON: length 17.2
  TOP w0.762: 51.6,98.87 J29.3 ; J29.3 53.18,97.29 ; J29.3 51.6,97.29 ; J29.3 53.18,98.87
  TOP w1.905: 58.73,114.96 J22.1 ; J22.1 60.5,113.2 ; J22.1 62.27,114.96 ; 59.19,98.35 J22.2 ; J22.2 61.81,100.98 ; J22.2 61.81,98.35 ; J22.2 59.19,100.98
EN1: length 39.7
  TOP w0.14: U5.23 111.17,61.55 v1(110.78,61.94)
  L3_INT1 w0.114: J3.2 92.23,84.66 110.78,66.1 v1(110.78,61.94)
EN1_IC: length 39
  BOTTOM w0.14: J73.12 58.32,70.12 58.65,70.44 58.65,78.57 66.11,86.03 81.5,86.03 82.66,87.2 J3.1
EN1_R: length 6.9
  TOP w0.14: R72.1 86.83,82.12 J3.3
  BOTTOM w0.14: J3.3 R2.1 C4.1
EN2: length 32.7
  TOP w0.14: U5.22 v1(111.67,61.94)
  BOTTOM w0.14: v1(111.67,61.94) 111.18,61.44 109.76,61.44 105.82,65.37 100.47,65.37 96.14,69.71 87.57,69.71 86.22,71.06 J4.2
EN2_IC: length 40.5
  BOTTOM w0.14: J4.1 78.13,79.56 60.37,79.56 59.06,78.25 59.06,68.18 58.45,67.58 J73.10
EN2_R: length 6.9
  TOP w0.14: J4.3 R73.1
  BOTTOM w0.14: J4.3 R6.1 C6.1
ERRMON1_IC: length 167.5
  L3_INT1 w0.114: J14.5 155.95,92.98 155.95,90.12 157.18,88.89 157.18,60.65 155.18,58.65 v1(155.18,38.82)
  BOTTOM w0.14: J6.6 65.87,40.7 72.46,47.29 93.1,47.29 93.34,47.05 93.34,45.87 106.37,32.85 142.27,32.85 148.24,38.82 v1(155.18,38.82)
ERRMON2_IC: length 168.2
  L3_INT1 w0.114: v1(152.38,34.5) 152.38,40.24 148.56,44.06 148.56,92.97 J13.5
  BOTTOM w0.14: v1(152.38,34.5) 144.59,26.71 100.68,26.71 85.88,41.51 70.75,41.51 67.4,38.16 J6.4
FCCU1_IC: length 119.3
  BOTTOM w0.14: J73.4 58.54,59.96 59.47,60.88 59.47,77.99 60.55,79.07 70.85,79.07 77.57,72.36 87.15,72.36 89.4,74.61 89.4,88.87 97.43,96.9 J12.3
FCCU2_IC: length 132.1
  BOTTOM w0.14: J73.2 58.54,57.42 59.88,58.75 59.88,77.75 60.74,78.62 70.61,78.62 77.17,72.05 87.44,72.05 89.8,74.41 89.8,88.51 97.78,96.5 133.17,96.5 134.04,95.63 141.35,95.63 142.62,96.9 J13.3
FS0B: length 87.6
  TOP w0.14: R30.1 C43.1 93.78,71.07 93.77,71.06 J8.2 ; U5.24 109.89,61.76 v1(109.89,61.94)
  L3_INT1 w0.114: J8.2 87.51,75.26 84.86,75.26 68.99,91.14 TP14.1
  BOTTOM w0.14: J8.2 92.68,70.1 96.23,70.1 100.42,65.91 106.47,65.91 109.89,62.48 v1(109.89,61.94)
FS0B_IC: length 109.1
  TOP w0.14: Q4.1 65.88,14.26 R71.1 65.71,18.09 63.75,20.05 63.75,44.1 J6.14 ; R28.1 J8.3
  BOTTOM w0.14: J6.14 58.45,50.86 60.28,52.7 60.28,77.44 61,78.16 70.44,78.16 76.9,71.7 81.3,71.7 83.31,69.69 85.91,69.69 87.07,68.52 J8.3
FS0B_VIN: length 2.6
  TOP w0.14: R29.1 J8.1
GPIO1_VDDOTP: length 82.8
  TOP w0.14: J14.2 J14.4 J14.6 J14.8 159.86,91.81 TP24.1 R44.1 v1(158.34,87.67) ; U5.4 112.17,55.13 v1(112.16,55.12)
  BOTTOM w0.14: v1(158.34,87.67) 157.86,87.19 142.98,87.19 132.59,76.8 132.59,64.15 132.56,64.11 132.56,64.04 124.17,55.66 112.73,55.66 112.19,55.12 v1(112.16,55.12)
  BOTTOM w0.381: v1(112.16,55.12) 112.16,55.02 C44.1
GPIO2_VMON3: length 60.7
  TOP w0.14: U5.14 115.38,59.43 v1(115.98,60.03) ; v1(139.58,87.3) GPIO2_VMON3.1 139.58,91.79 J12.8 J12.6 J12.4 J12.2
  BOTTOM w0.14: C34.1 115.98,60.03 v1(115.98,60.03) 115.41,60.6 115.41,62.45 117.41,64.44 117.41,80.04 124.67,87.3 v1(139.58,87.3)
GPIO3_VMON4: length 69.8
  TOP w0.14: v1(149.75,87.65) GPIO3_VMON4.1 149.75,91.78 J13.8 J13.6 J13.4 J13.2 ; U5.13 115.77,58.93 v1(115.98,59.14)
  BOTTOM w0.14: v1(149.75,87.65) 142.98,87.65 132.25,76.92 132.25,64.17 124.11,56.04 120.22,56.04 117.68,58.57 116.18,58.57 115.98,58.78 v1(115.98,59.14) 116.83,59.14 C53.1
GPO1_IC: length 177.7
  TOP w0.14: J14.3 R43.2 v1(154.53,96.17)
  L3_INT1 w0.114: v1(154.53,33.14) 153.68,33.99 153.68,95.32 v1(154.53,96.17)
  BOTTOM w0.14: J6.1 54.73,35.62 55.94,36.83 76.02,36.83 77.99,38.8 85.97,38.8 99.68,25.09 146.47,25.09 v1(154.53,33.14)
GPO2_IC: length 164.3
  TOP w0.14: 134.24,99.44 135.99,99.44 135.99,99.44 J12.1
  L3_INT1 w0.114: v1(135.71,30.08) 135.71,48.16 138.35,50.8 138.35,98.09 J12.1
  BOTTOM w0.14: J6.3 55.71,39.43 66.14,39.43 72,45.3 92.34,45.3 107.56,30.08 v1(135.71,30.08)
GPO3_IC: length 164.2
  TOP w0.14: R42.2 146.15,99.44 146.15,99.44 J13.1
  L3_INT1 w0.114: J13.1 145.78,98.04 v1(145.78,40)
  BOTTOM w0.14: J6.5 54.46,40.7 55.65,41.89 64.99,41.89 71.46,48.36 93.94,48.36 106.51,35.78 141.56,35.78 v1(145.78,40)
I2C_SCL_IC: length 92.2
  TOP w0.14: U5.2 111.17,55.91 v1(110.39,55.12) ; v1(63.01,77.45) 63.01,79.25 62.87,79.39 R65.2 62.15,79.39 R64.2
  L3_INT1 w0.114: TP17.1 41.23,76.46 62.02,76.46 v1(63.01,77.45)
  BOTTOM w0.14: R8.2 109.53,54.26 v1(110.39,55.12) 110.39,56.15 109.6,56.94 109.6,60.36 105.99,63.96 79.51,63.96 69.59,73.88 63.58,73.88 63.01,74.45 v1(63.01,77.45)
I2C_SDA_IC: length 89.4
  TOP w0.14: U5.3 111.67,55.52 v1(111.28,55.12) ; v1(63.85,74.84) 63.11,74.84 62.97,74.98 62.97,75.63 62.74,75.86 R66.2 62.16,75.86 R67.2
  L3_INT1 w0.114: TP18.1 40.94,73.97 60.85,73.97 61.72,74.84 v1(63.85,74.84)
  BOTTOM w0.14: v1(63.85,74.84) 70.66,74.84 80.54,64.96 105.53,64.96 109.97,60.52 109.97,57.4 111.28,56.09 v1(111.28,55.12) 111.25,55.12 R9.2
PGOOD1_IC: length 133.9
  TOP w0.14: Q2.1 72.23,14.26 R69.1 72.06,16.75 65.58,23.22 65.58,46.85 55.79,56.64 55.79,63.9 J73.8 R18.2 v1(65.58,65.04) ; v1(109.03,60.27) 109.37,59.93 U5.26
  L3_INT1 w0.114: J73.8 55.58,63.69 41.63,63.69 TP12.1
  BOTTOM w0.14: v1(109.03,60.27) 106.95,62.36 68.25,62.36 v1(65.58,65.04)
PGOOD2_IC: length 136.6
  TOP w0.14: R19.2 62.08,64.07 61.94,64.22 60.71,64.22 58.99,62.5 J73.6 ; R19.2 61.28,63.51 61.14,63.37 61.14,54.39 67.33,48.2 67.33,25.22 69.99,22.56 73.71,22.56 78.41,17.86 R70.1 78.41,13.59 78.58,13.41 Q3.1 ; R19.2 v1(62.08,62.79) ; v1(109.03,59.39) 109.08,59.43 U5.27
  L3_INT1 w0.114: TP13.1 41.33,61.21 55.64,61.21 J73.6
  BOTTOM w0.14: v1(62.08,62.79) 63.59,61.29 107.13,61.29 v1(109.03,59.39)
SW1FB: length 7.7
  TOP w0.14: U5.25 109.82,60.73 v1(105.13,60.73)
  BOTTOM w0.14: R59.1 104.41,59.82 R11.1 C49.2 v1(105.13,60.73)
SW1FB_R: length 22.8
  TOP w0.14: R60.1 104.59,76.8 104.59,62.73 v1(102.59,60.73)
  BOTTOM w0.14: R11.2 C49.1 v1(102.59,60.73)
SW1LX1: length 1.1
  BOTTOM w0.508: C12.2 v1(112.56,61.94)
SW1OUT: length 37.5
  TOP w1.905: 107.37,98.33 J23.2 ; J23.2 109.99,100.96 ; J23.2 109.99,98.33 ; J23.2 107.37,100.96 ; 106.91,114.95 J23.1 ; J23.1 110.44,114.95 ; J23.1 108.68,113.18
  L3_INT1 w0.305: J23.1 108.75,114.88 112.75,114.88 114.13,113.5 TP15.1
  L6_PWR2 w0.686: 107.37,100.96 J23.2 ; J23.2 109.99,98.33 ; J23.2 107.37,98.33 ; J23.2 109.99,100.96 ; 108.68,113.18 J23.1 ; J23.1 110.44,114.95 ; J23.1 106.91,114.95
SW2BOOT: length 3.2
  TOP w0.254: v1(116.99,58.1) 116.26,58.1 115.93,58.43 U5.12
  BOTTOM w0.254: C19.1 117.16,58.1 v1(116.99,58.1)
SW2COMP: length 18
  TOP w0.254: J94.2 107.91,47.84 112.05,51.98 112.05,53.84 112.67,54.46 U5.5
SW2CSN: length 48.2
  TOP w0.305: U5.7 113.67,55.13 v1(113.68,55.12) ; R75.2 v2(141.34,41.61)
  L6_PWR2 w0.305: v2(138.38,48.76) 138.38,47.19 140.64,44.93 140.64,44.9 140.72,44.82 140.72,42.23 v2(141.34,41.61) 140.68,40.96 137.02,40.96 135.85,42.13 123.42,42.13 113.94,51.61 113.94,54.86 v1(113.68,55.12)
  BOTTOM w0.305: C37.2 v1(113.68,55.12)
  BOTTOM w0.508: R77.1 v2(138.38,48.76)
SW2CSP: length 50.4
  TOP w0.305: U5.8 114.17,55.52 v1(114.57,55.12) ; R12.2 v2(139.64,41.55)
  L6_PWR2 w0.305: v1(114.57,55.12) 114.42,54.97 114.42,51.79 123.47,42.75 135.97,42.75 137.16,41.55 v2(139.64,41.55) 140.17,42.08 140.17,44.74 136.79,48.11 v2(131.61,48.11)
  BOTTOM w0.305: C37.1 114.7,54.99 v1(114.57,55.12) ; R76.1 131.64,48.28 131.61,48.25 v2(131.61,48.11)
SW2FB: length 6
  TOP w0.254: U5.6 v1(113.17,53.31)
  BOTTOM w0.254: R63.1 113.95,53.31 v1(113.17,53.31)
  BOTTOM w0.305: C50.2 R61.1 R63.1
SW2FB_R: length 35.4
  TOP w0.508: R27.1 v2(146.96,48.06)
  L6_PWR2 w0.508: v2(116.3,51.13) 125.59,51.13 127.09,49.63 138.79,49.63 139.36,49.06 145.96,49.06 v2(146.96,48.06)
  BOTTOM w0.508: v2(116.3,51.13) 116.26,51.17 C50.1 R61.2
SW2GHS: length 15.8
  TOP w0.254: U5.11 115.67,57.93 v1(115.84,57.76) ; v1(118.98,58.29) 128.29,58.29 128.69,58.69 Q15.4
  L3_INT1 w0.254: v1(115.84,57.76) 116.02,57.58 118.28,57.58 v1(118.98,58.29)
  BOTTOM w0.254: R24.1 v1(118.98,58.29)
SW2GLS: length 25
  TOP w0.254: v1(135.87,54.26) 136.4,53.73 R25.1 Q16.4 ; v1(115.73,56.47) 114.98,56.47 114.72,56.73 U5.9
  L6_PWR2 w0.254: v1(115.73,56.47) 133.66,56.47 v1(135.87,54.26)
SW2LX: length 20.4
  TOP w0.254: U5.10 115.38,57.43 115.75,57.06 v1(116.66,57.06) ; Q15.3 129.7,59.43 129.6,59.53 121.11,59.53 v1(120.72,59.14)
  L3_INT1 w0.254: v1(116.66,57.06) 118.64,57.06 v1(120.72,59.14)
  BOTTOM w0.254: C19.2 117.06,56.66 v1(116.66,57.06) ; R24.2 v1(120.72,59.14)
  BOTTOM w0.508: C51.1 v2(131.09,60.15) ; R3.1 v2(131.22,53.26)
SW2OUT: length 56.5
  TOP w0.686: 169.41,64.56 TP16.1 ; TP16.1 171.55,64.56 ; TP16.1 171.55,66.7
  TOP w1.905: J24.2 159,56.07 ; J24.2 159,53.44 ; J24.2 156.37,56.07 ; J24.2 156.37,53.44 ; J24.1 172.98,56.52 ; J24.1 171.22,54.76 ; J24.1 172.98,52.99
  L4_PWR1 w0.686: TP16.1 171.55,64.56 ; TP16.1 169.41,64.56 ; TP16.1 169.41,66.7 ; TP16.1 171.55,66.7
  L4_PWR1 w1.905: J24.1 172.98,56.52 ; J24.1 172.98,52.99 ; J24.1 171.22,54.76 ; 156.37,53.44 J24.2 ; J24.2 159,56.07 ; J24.2 159,53.44 ; J24.2 156.37,56.07
  L6_PWR2 w0.686: TP16.1 171.55,66.7 ; TP16.1 169.41,64.56 ; TP16.1 171.55,64.56
  L6_PWR2 w1.905: 171.22,54.76 J24.1 ; J24.1 172.98,52.99 ; J24.1 172.98,56.52 ; 156.37,53.44 J24.2 ; J24.2 159,53.44 ; J24.2 156.37,56.07 ; J24.2 159,56.07
  BOTTOM w0.508: C52.2 134.29,51.64 R74.2 v2(135.16,50.52) ; R77.2 v2(137.38,51.16)
  vias: v2(143.7,49.81) v2(143.78,43.03) v2(146.77,45.38) v2(147.95,43.03) v2(149.58,63.56) v2(149.87,44.94) v2(152.93,63.92) v2(154.41,62.04) v2(155.43,62.04) v2(156.44,62.04) v2(157.95,62) v2(158.46,50.03) v2(158.97,62) v2(159.99,62) v2(161.69,62.01) v2(162.7,62.01) v2(163.54,50.03) v2(163.72,62.01) v2(165.27,61.98) v2(166.29,61.98) v2(167.3,61.98) v2(168.62,50.03) v2(173.7,50.03) v2(174.19,67.61) v2(174.19,62.53) v2(174.19,57.45) v2(174.19,52.37)
